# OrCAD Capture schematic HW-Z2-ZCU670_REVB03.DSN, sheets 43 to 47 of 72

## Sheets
43 043 Power Input Fan Controller: size Custom
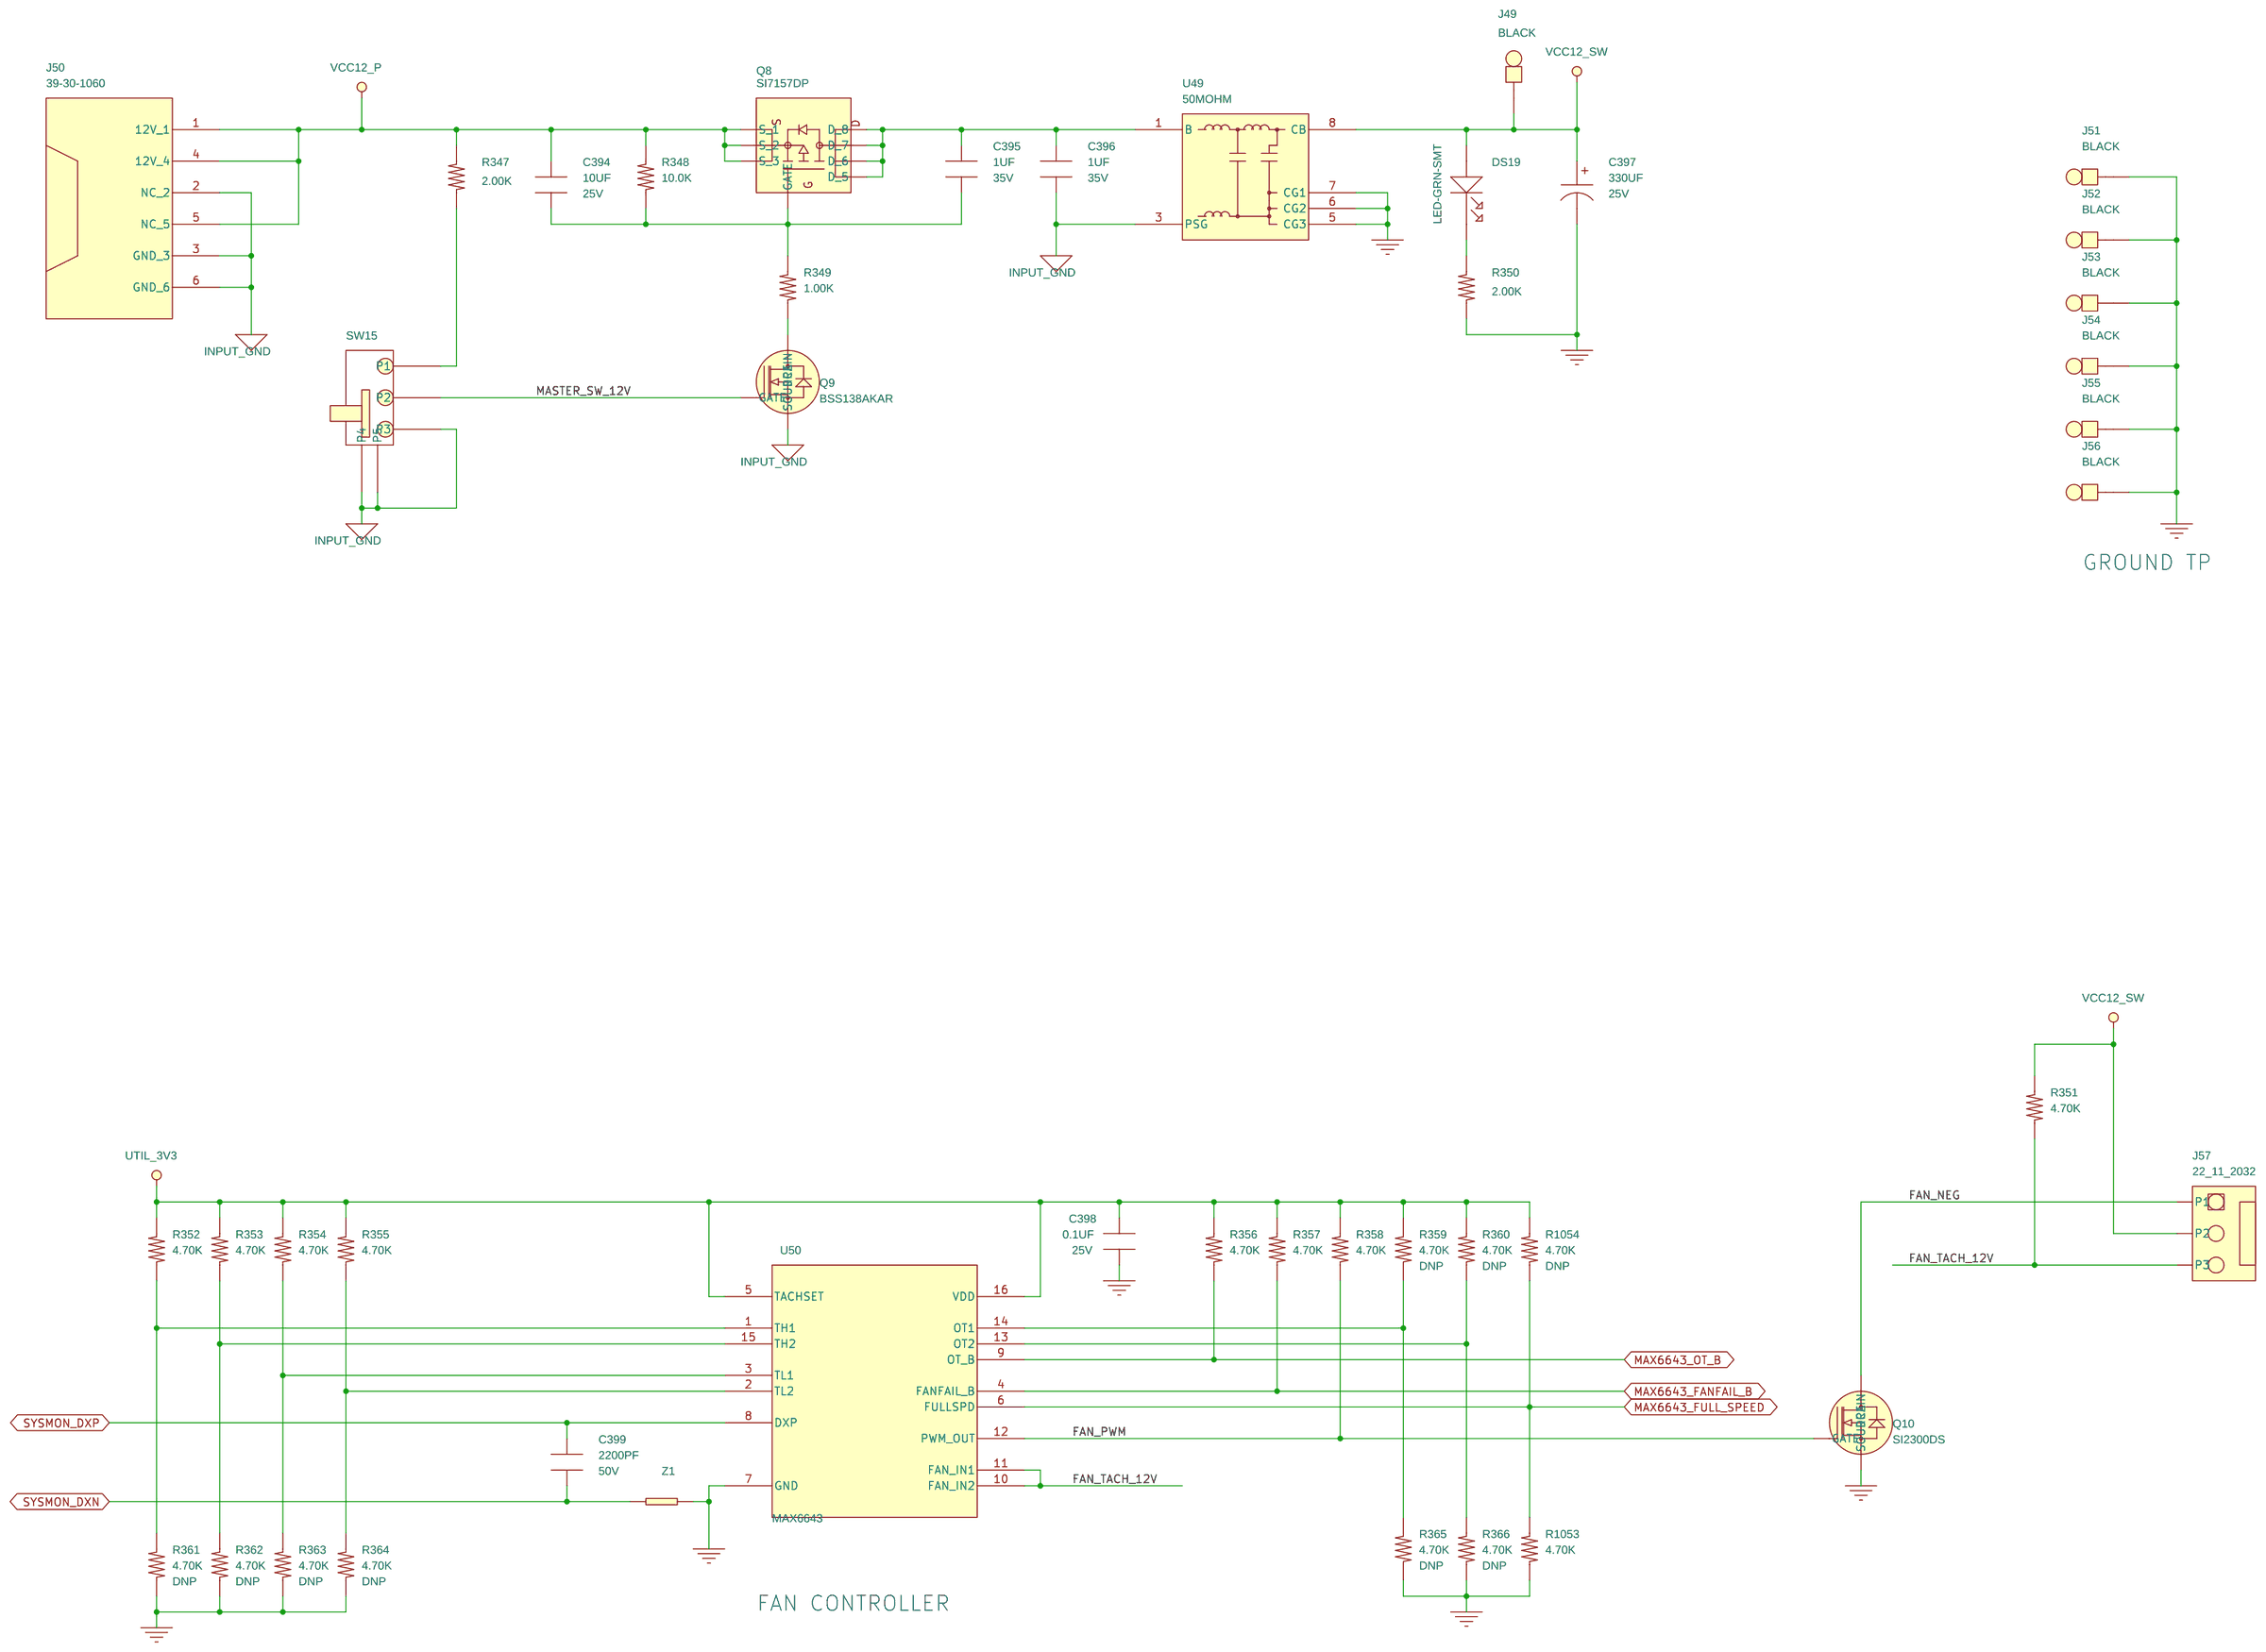
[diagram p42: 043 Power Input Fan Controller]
44 044 VCCINT - VCCINT_AMS PMIC1: size Custom
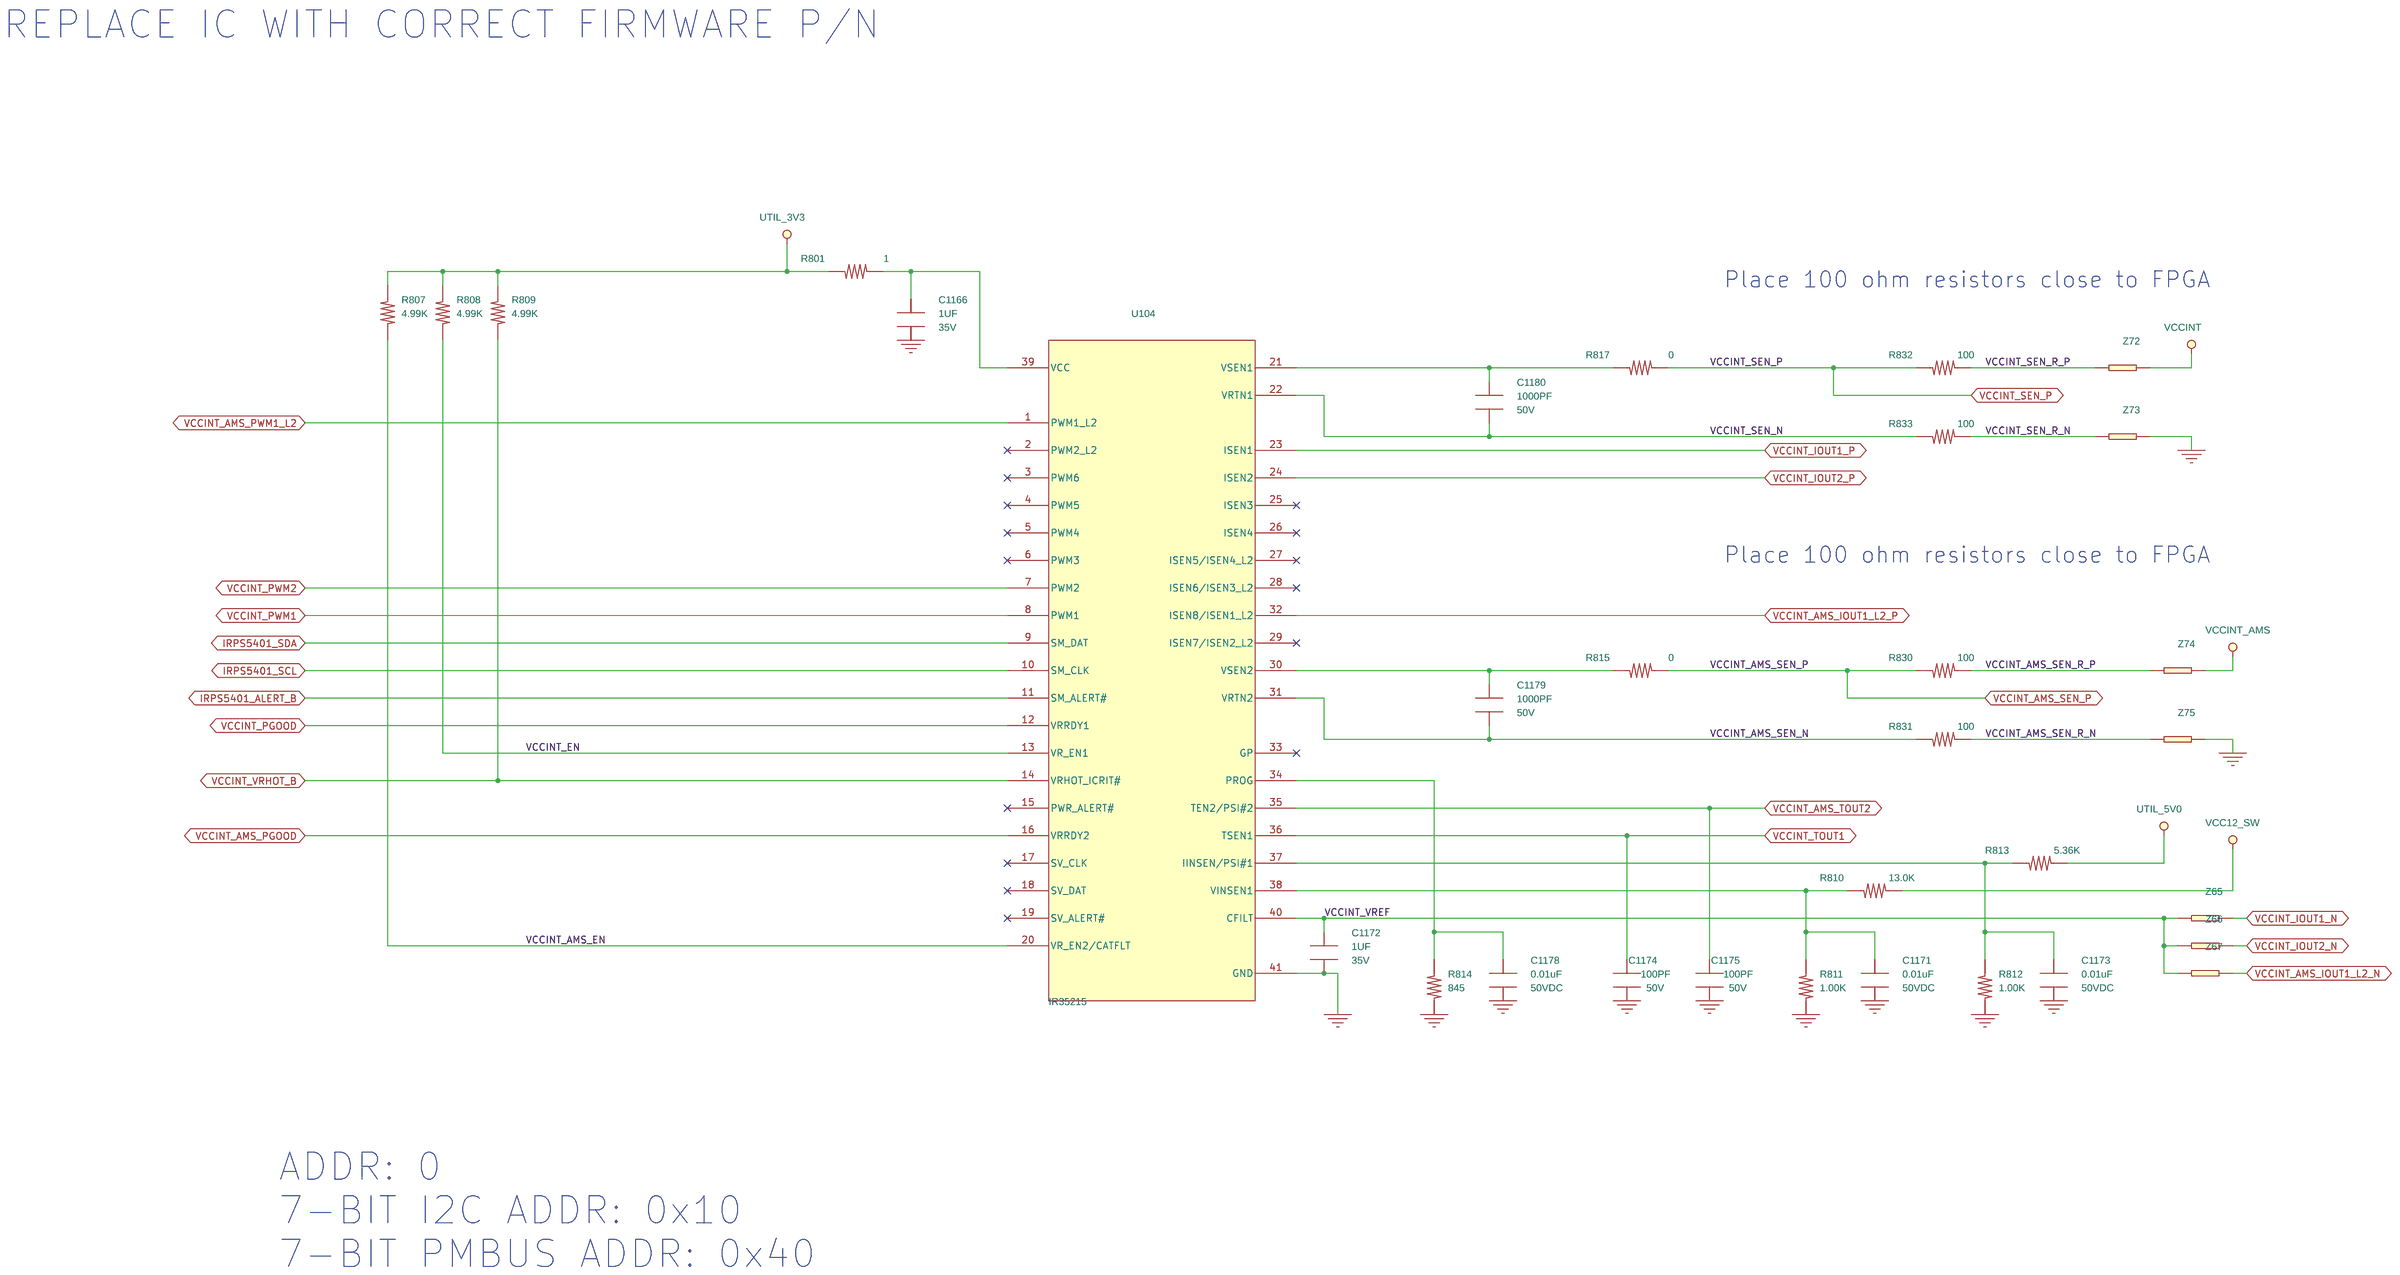
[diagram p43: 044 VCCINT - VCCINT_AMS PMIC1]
45 045 VCCINT - VCCINT_AMS Stages: size Custom
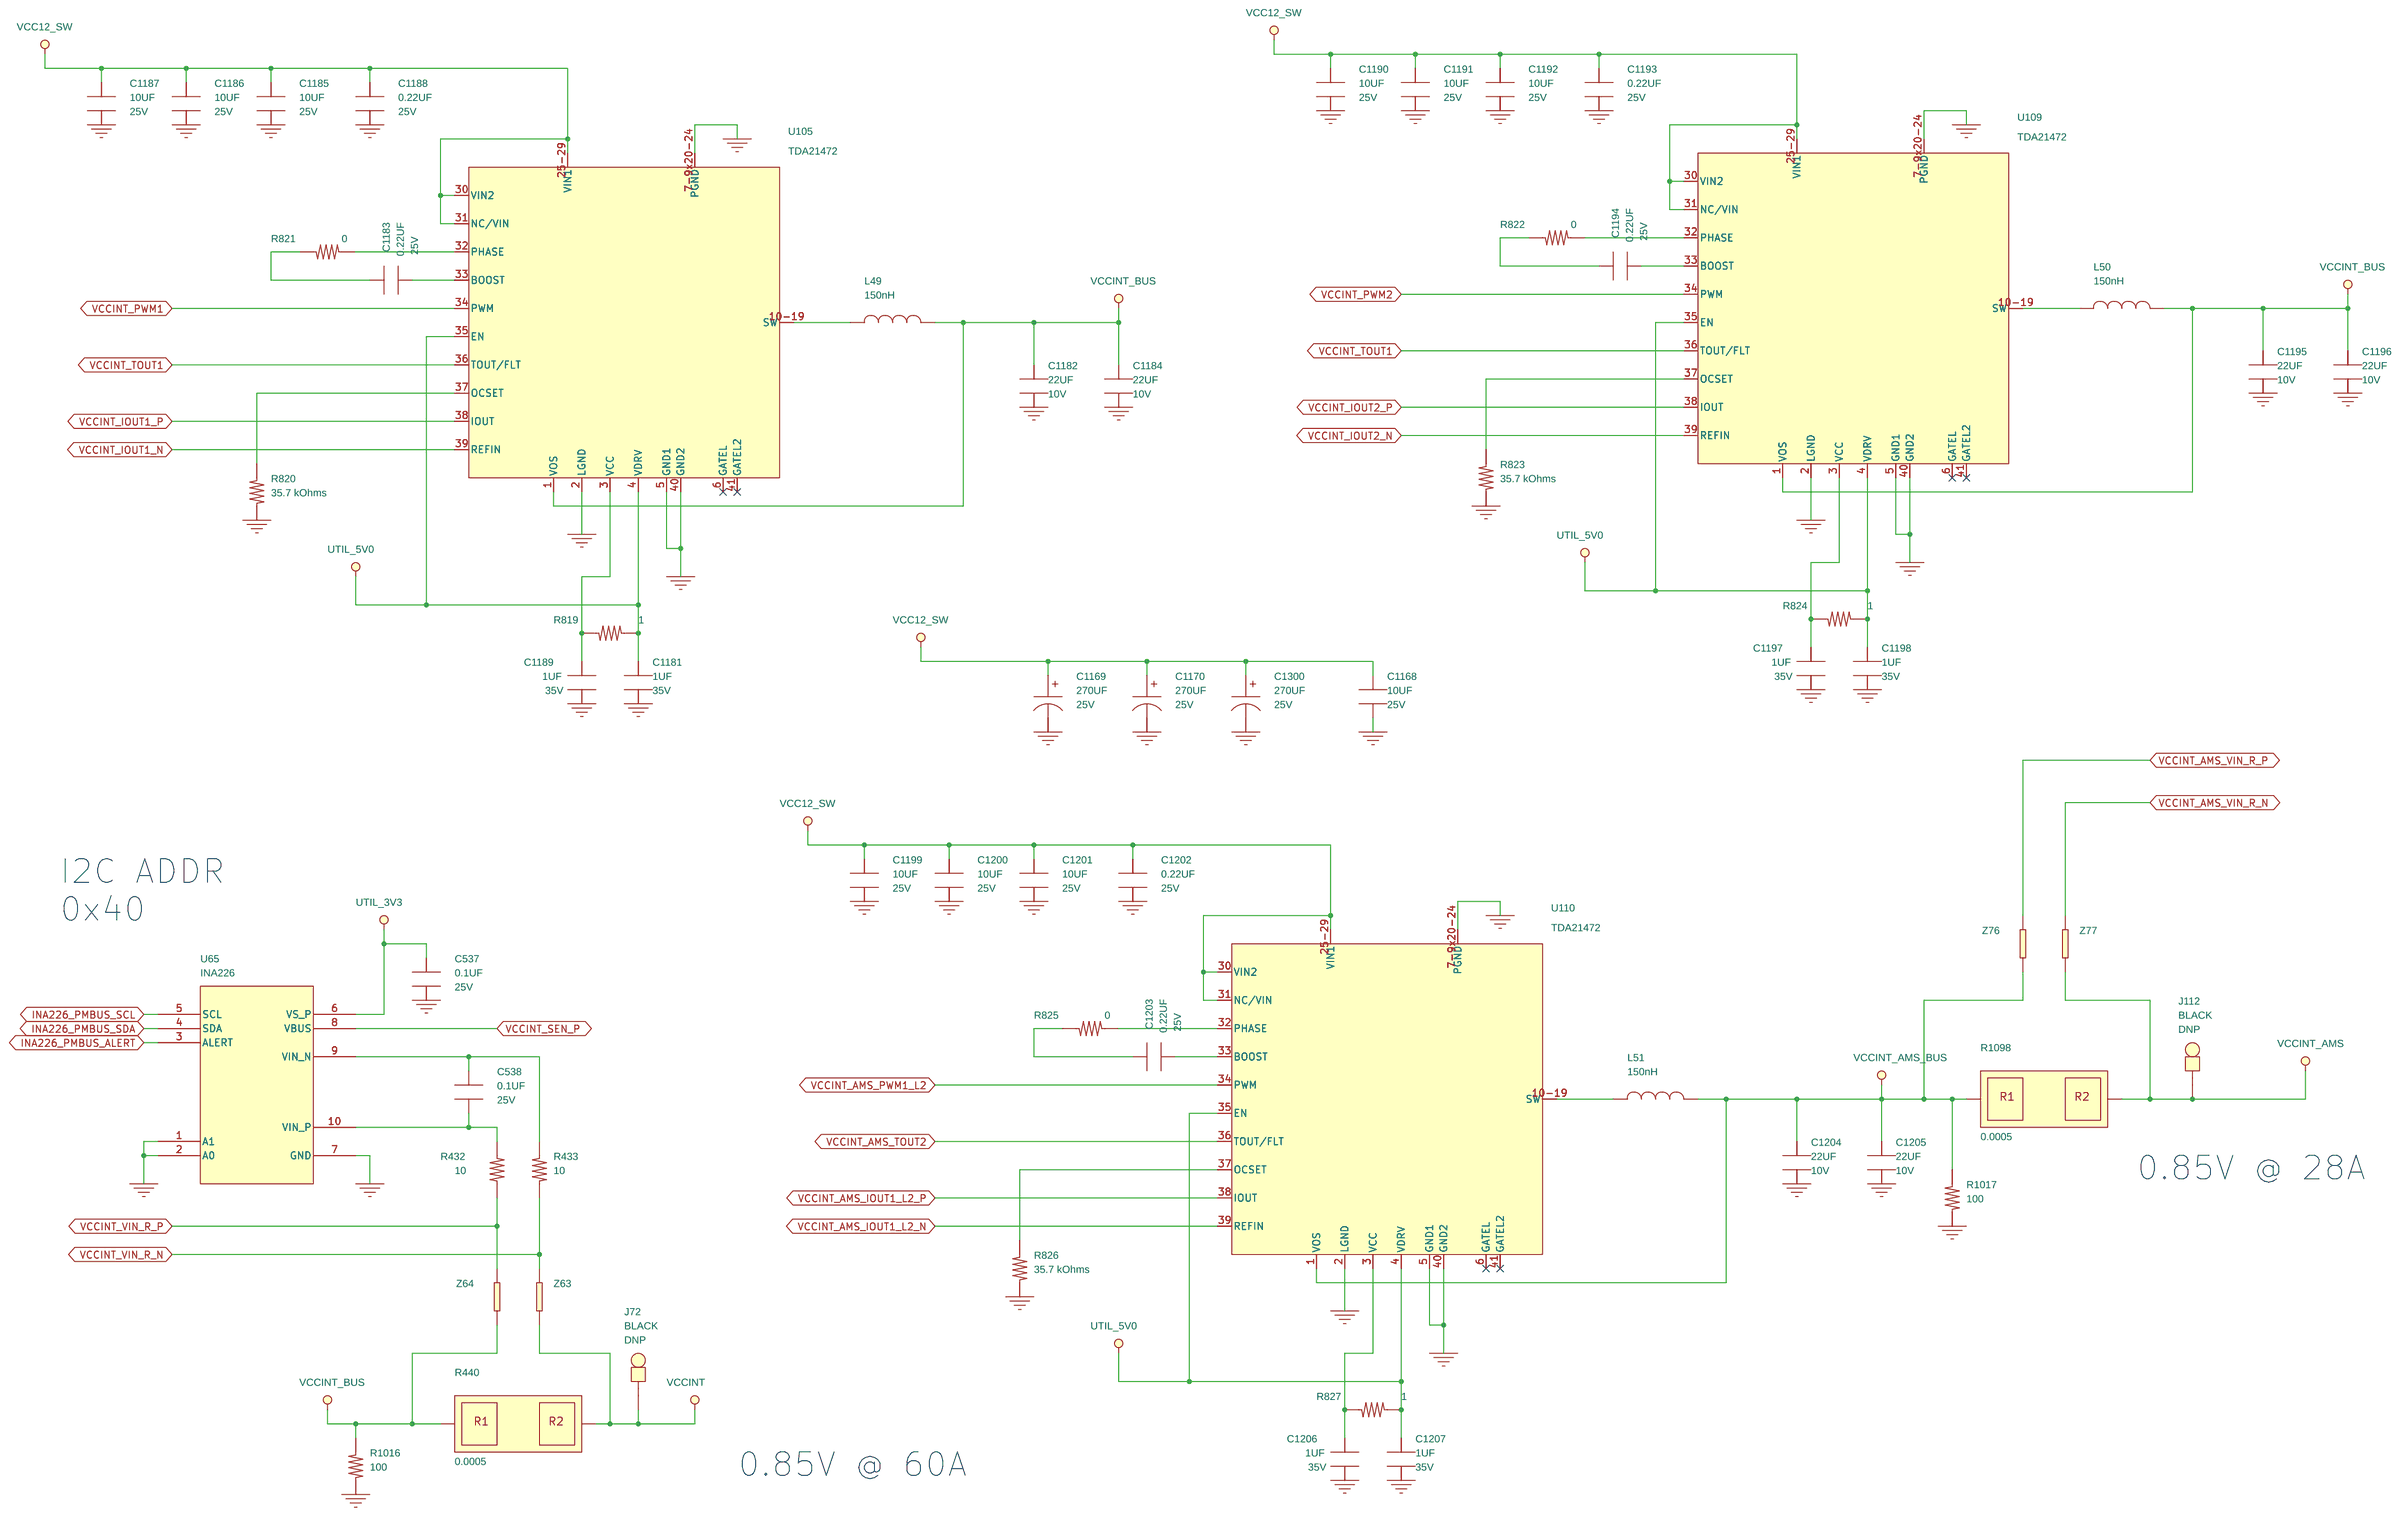
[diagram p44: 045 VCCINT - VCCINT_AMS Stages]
46 046 VCCINT - VCCINT_AMS Decap: size Custom
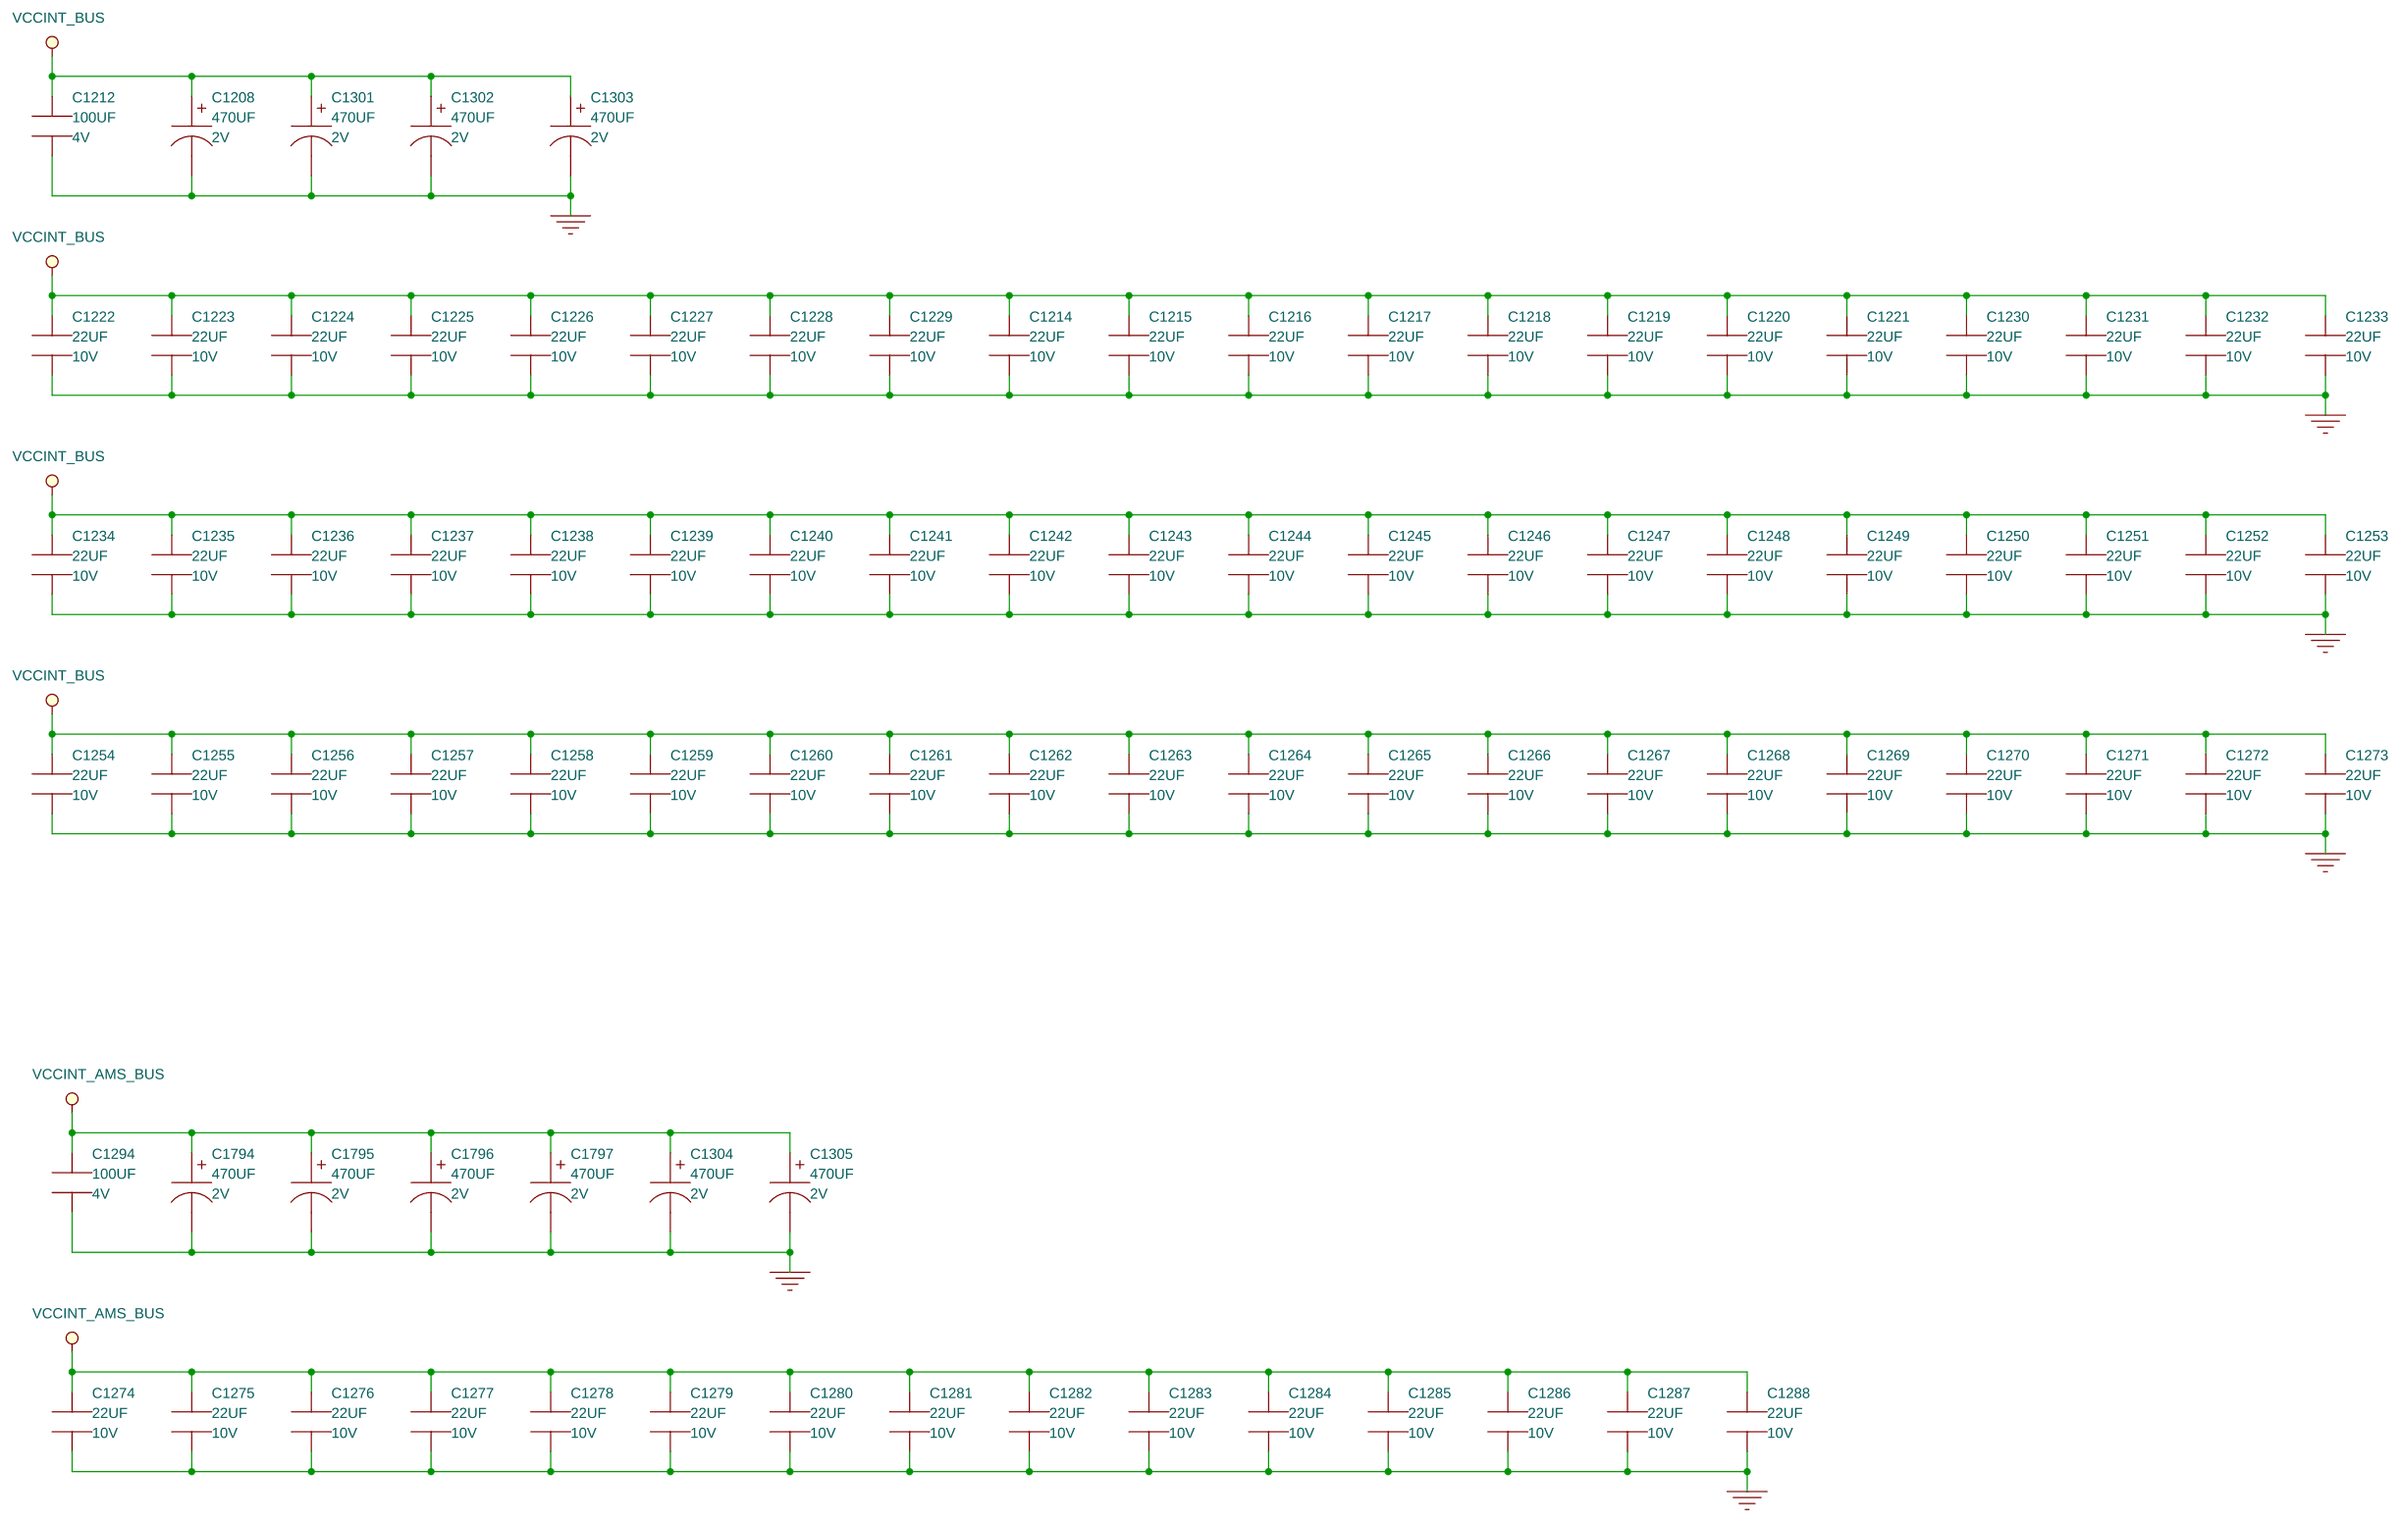
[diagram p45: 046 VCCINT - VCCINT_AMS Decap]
47 047 PMIC 2: size Custom
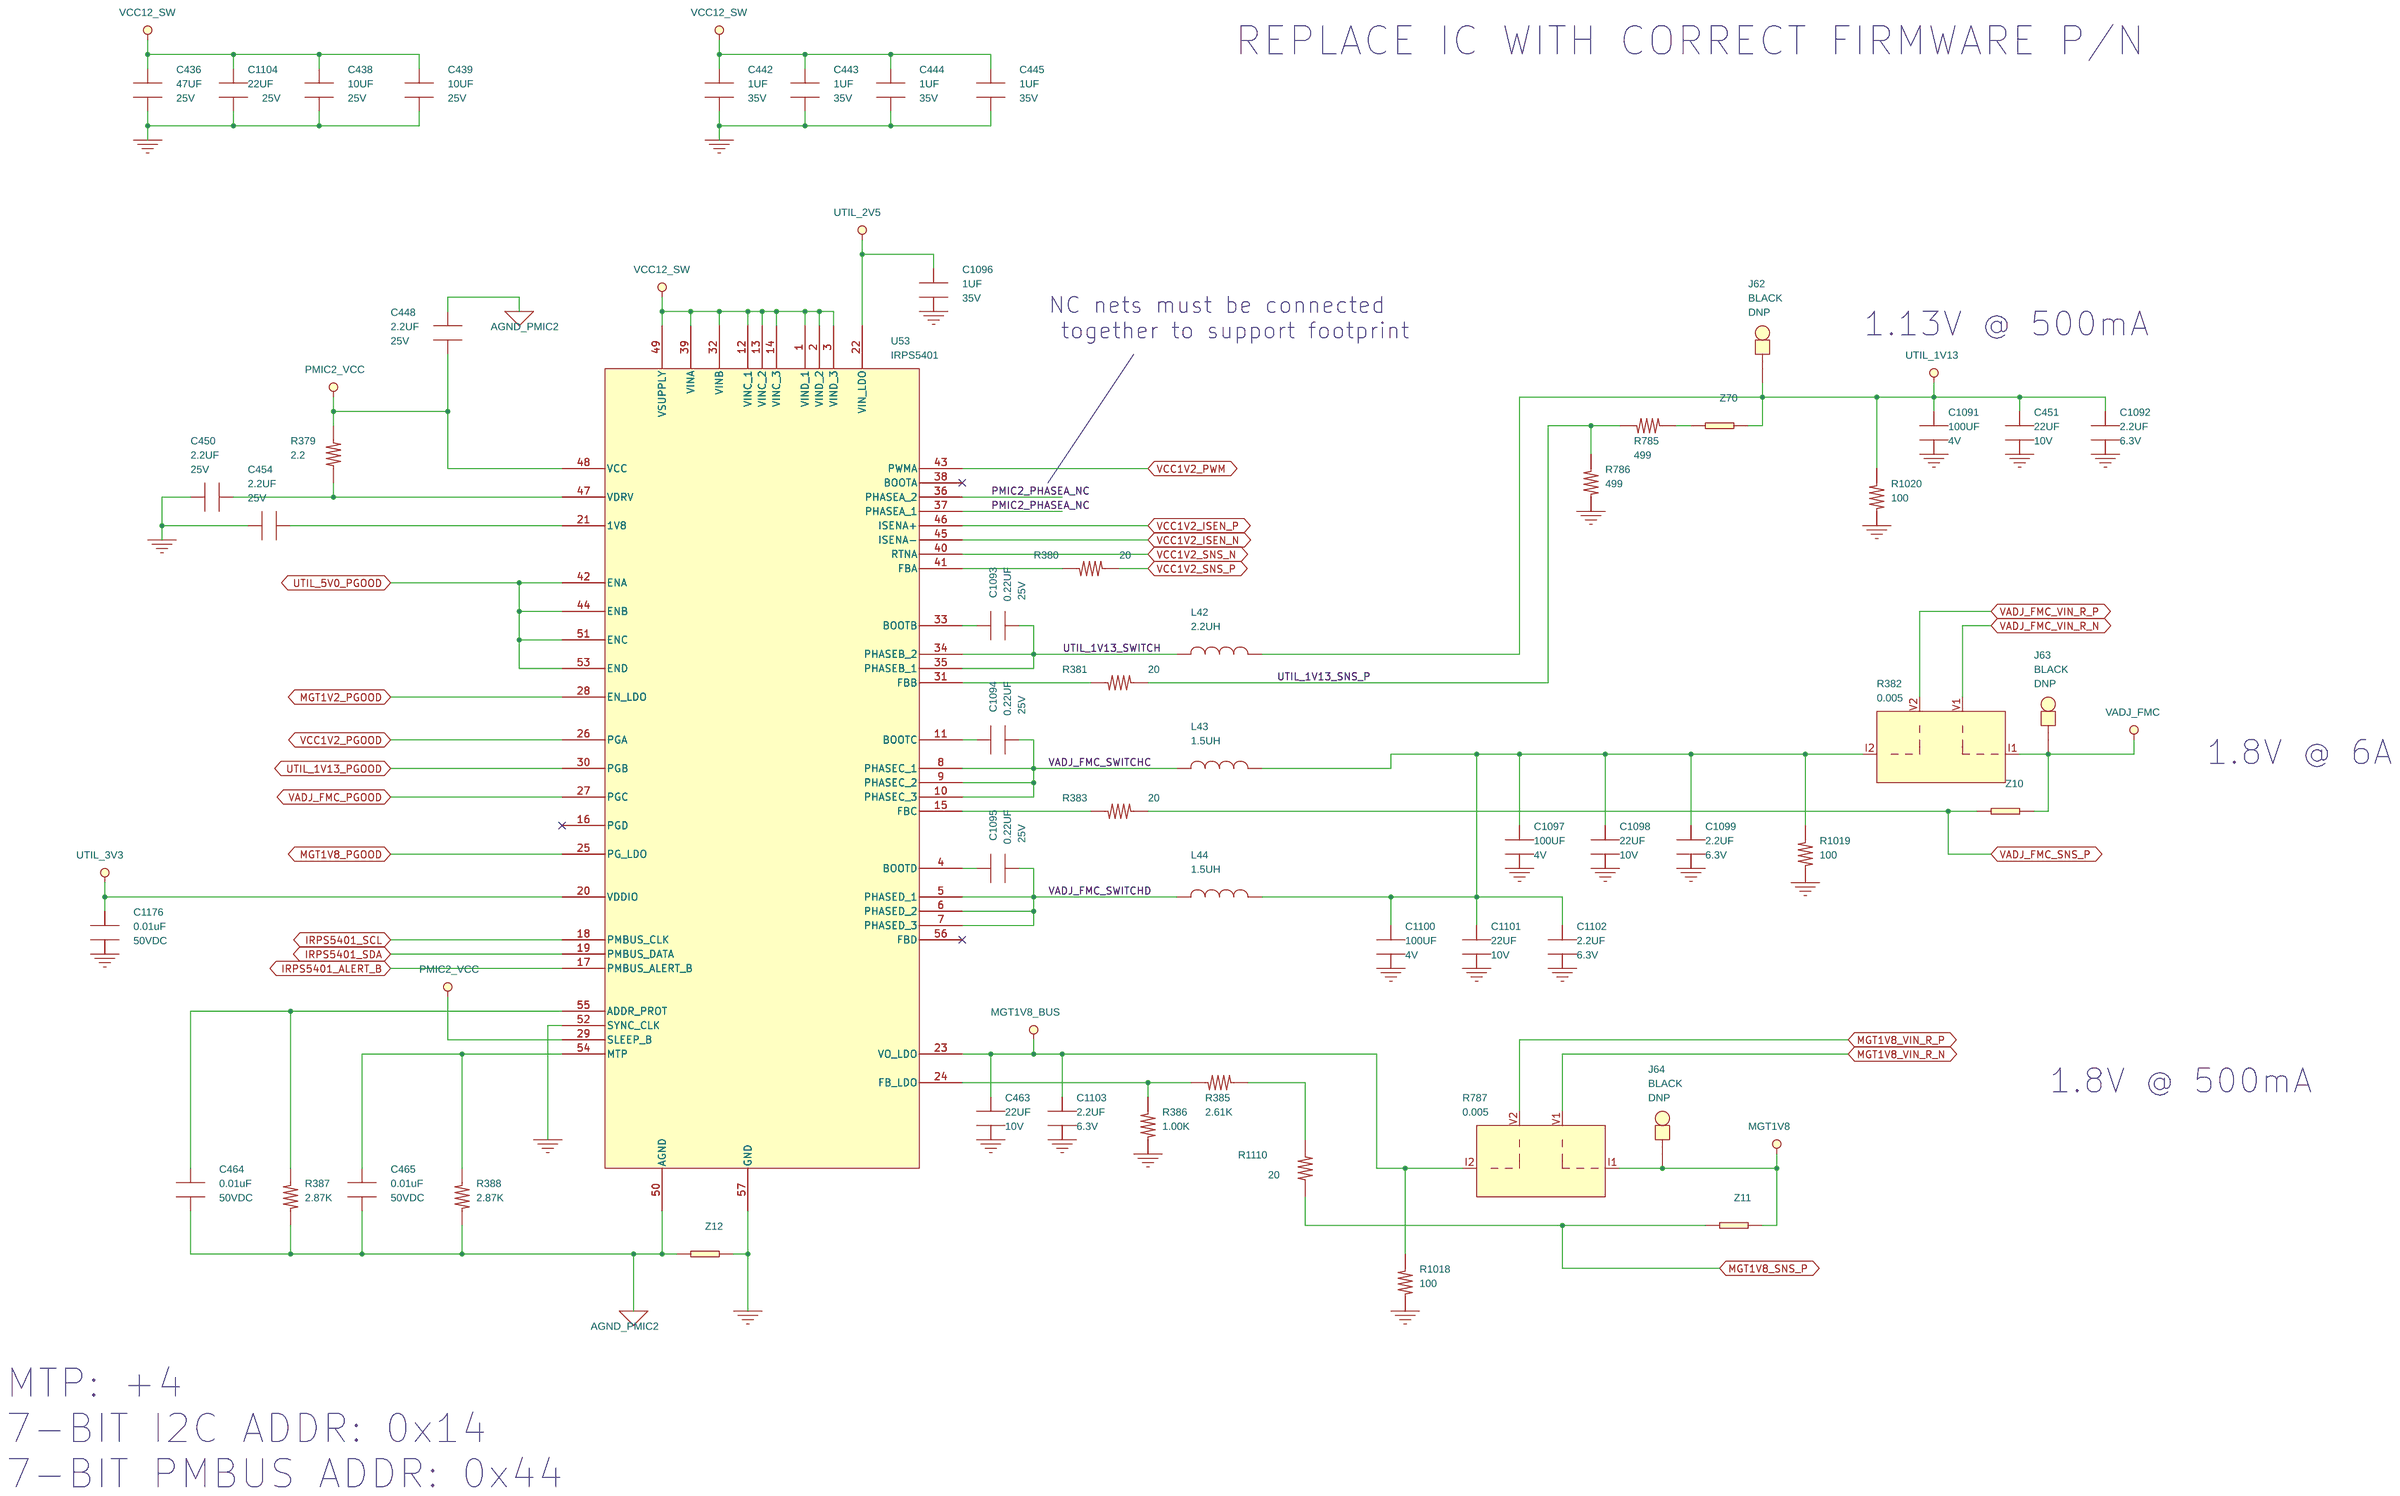
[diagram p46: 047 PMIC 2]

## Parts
sheet 043 Power Input Fan Controller
C394  10UF  [CAPC320X250X220]
C395  1UF  [CAPC100X50X60]
C396  1UF  [CAPC100X50X60]
C397  330UF  [CAPR_800_350]
C398  0.1UF  [CAPC100X50X55]
C399  2200PF  [CAPC100X50X55]
DS19  LED-GRN-SMT  [LED_0603]
J49  BLACK  [TP_KEY_MINI]
J50  39-30-1060  [CON_MOL_5569_6P]
J51  BLACK  [TP_KEY_MINI]
J52  BLACK  [TP_KEY_MINI]
J53  BLACK  [TP_KEY_MINI]
J54  BLACK  [TP_KEY_MINI]
J55  BLACK  [TP_KEY_MINI]
J56  BLACK  [TP_KEY_MINI]
J57  22_11_2032  [HDR_1X3_LOCK_MOLEX]
Q8  SI7157DP  [PWR_56_V02]
Q9  BSS138AKAR  [SOT_23]
Q10  SI2300DS  [SOT_23]
R347  2.00K  [RESC100X50X40]
R348  10.0K  [RESC100X50X40]
R349  1.00K  [RESC100X50X40]
R350  2.00K  [RESC100X50X40]
R351  4.70K  [RESC100X50X40]
R352  4.70K  [RESC100X50X40]
R353  4.70K  [RESC100X50X40]
R354  4.70K  [RESC100X50X40]
R355  4.70K  [RESC100X50X40]
R356  4.70K  [RESC100X50X40]
R357  4.70K  [RESC100X50X40]
R358  4.70K  [RESC100X50X40]
R359  4.70K  [RESC100X50X40]
R360  4.70K  [RESC100X50X40]
R361  4.70K  [RESC100X50X40]
R362  4.70K  [RESC100X50X40]
R363  4.70K  [RESC100X50X40]
R364  4.70K  [RESC100X50X40]
R365  4.70K  [RESC100X50X40]
R366  4.70K  [RESC100X50X40]
R1053  4.70K  [RESC100X50X40]
R1054  4.70K  [RESC100X50X40]
SW15  1101M2S3AQE2  [SW_102_1261_EV]
U49  50MOHM  [MURATA_BNX01]
U50  MAX6643  [QSOP16_MAX_E16_1]
Z1  0201_SHORT  [0201_SHORT]
sheet 044 VCCINT - VCCINT_AMS PMIC1
C1166  1UF  [CAPC100X50X60]
C1171  0.01uF  [CAPC100X50X55]
C1172  1UF  [CAPC100X50X60]
C1173  0.01uF  [CAPC100X50X55]
C1174  100PF  [CAPC100X50X55]
C1175  100PF  [CAPC100X50X55]
C1178  0.01uF  [CAPC100X50X55]
C1179  1000PF  [CAPC100X50X55]
C1180  1000PF  [CAPC100X50X55]
R801  1  [RESC160X80X55]
R807  4.99K  [RESC100X50X40]
R808  4.99K  [RESC100X50X40]
R809  4.99K  [RESC100X50X40]
R810  13.0K  [RESC100X50X40]
R811  1.00K  [RESC100X50X40]
R812  1.00K  [RESC100X50X40]
R813  5.36K  [RESC100X50X40]
R814  845  [RESC100X50X40]
R815  0  [RESC100X50X40]
R817  0  [RESC100X50X40]
R830  100  [RESC100X50X40]
R831  100  [RESC100X50X40]
R832  100  [RESC100X50X40]
R833  100  [RESC100X50X40]
U104  IR35215  [QFN04P500X500X85_40_370]
Z65  0201_SHORT  [0201_SHORT]
Z66  0201_SHORT  [0201_SHORT]
Z67  0201_SHORT  [0201_SHORT]
Z72  0201_SHORT  [0201_SHORT]
Z73  0201_SHORT  [0201_SHORT]
Z74  0201_SHORT  [0201_SHORT]
Z75  0201_SHORT  [0201_SHORT]
sheet 045 VCCINT - VCCINT_AMS Stages
C537  0.1UF  [CAPC100X50X55]
C538  0.1UF  [CAPC100X50X55]
C1168  10UF  [CAPC320X250X220]
C1169  270UF  [CAPR_800_350]
C1170  270UF  [CAPR_800_350]
C1181  1UF  [CAPC100X50X60]
C1182  22UF  [CAPC200X125X145]
C1183  0.22UF  [CAPC100X50X55]
C1184  22UF  [CAPC200X125X145]
C1185  10UF  [CAPC320X250X220]
C1186  10UF  [CAPC320X250X220]
C1187  10UF  [CAPC320X250X220]
C1188  0.22UF  [CAPC100X50X55]
C1189  1UF  [CAPC100X50X60]
C1190  10UF  [CAPC320X250X220]
C1191  10UF  [CAPC320X250X220]
C1192  10UF  [CAPC320X250X220]
C1193  0.22UF  [CAPC100X50X55]
C1194  0.22UF  [CAPC100X50X55]
C1195  22UF  [CAPC200X125X145]
C1196  22UF  [CAPC200X125X145]
C1197  1UF  [CAPC100X50X60]
C1198  1UF  [CAPC100X50X60]
C1199  10UF  [CAPC320X250X220]
C1200  10UF  [CAPC320X250X220]
C1201  10UF  [CAPC320X250X220]
C1202  0.22UF  [CAPC100X50X55]
C1203  0.22UF  [CAPC100X50X55]
C1204  22UF  [CAPC200X125X145]
C1205  22UF  [CAPC200X125X145]
C1206  1UF  [CAPC100X50X60]
C1207  1UF  [CAPC100X50X60]
C1300  270UF  [CAPR_800_350]
J72  BLACK  [TP_KEY_MINI]
J112  BLACK  [TP_KEY_MINI]
L49  150nH  [IND_EATON_FP10007R3]
L50  150nH  [IND_EATON_FP10007R3]
L51  150nH  [IND_EATON_FP10007R3]
R432  10  [RESC100X50X40]
R433  10  [RESC100X50X40]
R440  0.0005  [RES_CSS2775]
R819  1  [RESC160X80X55]
R820  35.7 kOhms  [RESC100X50X40]
R821  0  [RESC100X50X40]
R822  0  [RESC100X50X40]
R823  35.7 kOhms  [RESC100X50X40]
R824  1  [RESC160X80X55]
R825  0  [RESC100X50X40]
R826  35.7 kOhms  [RESC100X50X40]
R827  1  [RESC160X80X55]
R1016  100  [RESC100X50X40]
R1017  100  [RESC100X50X40]
R1098  0.0005  [RES_CSS2775]
U65  INA226  [DGS_MSOP_10]
U105  TDA21472  [PQFN_TDA21472_41]
U109  TDA21472  [PQFN_TDA21472_41]
U110  TDA21472  [PQFN_TDA21472_41]
Z63  0201_SHORT  [0201_SHORT]
Z64  0201_SHORT  [0201_SHORT]
Z76  0201_SHORT  [0201_SHORT]
Z77  0201_SHORT  [0201_SHORT]
sheet 046 VCCINT - VCCINT_AMS Decap
C1208  470UF  [TANT_D]
C1212  100UF  [CAPC200X125X145]
C1214  22UF  [CAPC200X125X145]
C1215  22UF  [CAPC200X125X145]
C1216  22UF  [CAPC200X125X145]
C1217  22UF  [CAPC200X125X145]
C1218  22UF  [CAPC200X125X145]
C1219  22UF  [CAPC200X125X145]
C1220  22UF  [CAPC200X125X145]
C1221  22UF  [CAPC200X125X145]
C1222  22UF  [CAPC200X125X145]
C1223  22UF  [CAPC200X125X145]
C1224  22UF  [CAPC200X125X145]
C1225  22UF  [CAPC200X125X145]
C1226  22UF  [CAPC200X125X145]
C1227  22UF  [CAPC200X125X145]
C1228  22UF  [CAPC200X125X145]
C1229  22UF  [CAPC200X125X145]
C1230  22UF  [CAPC200X125X145]
C1231  22UF  [CAPC200X125X145]
C1232  22UF  [CAPC200X125X145]
C1233  22UF  [CAPC200X125X145]
C1234  22UF  [CAPC200X125X145]
C1235  22UF  [CAPC200X125X145]
C1236  22UF  [CAPC200X125X145]
C1237  22UF  [CAPC200X125X145]
C1238  22UF  [CAPC200X125X145]
C1239  22UF  [CAPC200X125X145]
C1240  22UF  [CAPC200X125X145]
C1241  22UF  [CAPC200X125X145]
C1242  22UF  [CAPC200X125X145]
C1243  22UF  [CAPC200X125X145]
C1244  22UF  [CAPC200X125X145]
C1245  22UF  [CAPC200X125X145]
C1246  22UF  [CAPC200X125X145]
C1247  22UF  [CAPC200X125X145]
C1248  22UF  [CAPC200X125X145]
C1249  22UF  [CAPC200X125X145]
C1250  22UF  [CAPC200X125X145]
C1251  22UF  [CAPC200X125X145]
C1252  22UF  [CAPC200X125X145]
C1253  22UF  [CAPC200X125X145]
C1254  22UF  [CAPC200X125X145]
C1255  22UF  [CAPC200X125X145]
C1256  22UF  [CAPC200X125X145]
C1257  22UF  [CAPC200X125X145]
C1258  22UF  [CAPC200X125X145]
C1259  22UF  [CAPC200X125X145]
C1260  22UF  [CAPC200X125X145]
C1261  22UF  [CAPC200X125X145]
C1262  22UF  [CAPC200X125X145]
C1263  22UF  [CAPC200X125X145]
C1264  22UF  [CAPC200X125X145]
C1265  22UF  [CAPC200X125X145]
C1266  22UF  [CAPC200X125X145]
C1267  22UF  [CAPC200X125X145]
C1268  22UF  [CAPC200X125X145]
C1269  22UF  [CAPC200X125X145]
C1270  22UF  [CAPC200X125X145]
C1271  22UF  [CAPC200X125X145]
C1272  22UF  [CAPC200X125X145]
C1273  22UF  [CAPC200X125X145]
C1274  22UF  [CAPC200X125X145]
C1275  22UF  [CAPC200X125X145]
C1276  22UF  [CAPC200X125X145]
C1277  22UF  [CAPC200X125X145]
C1278  22UF  [CAPC200X125X145]
C1279  22UF  [CAPC200X125X145]
C1280  22UF  [CAPC200X125X145]
C1281  22UF  [CAPC200X125X145]
C1282  22UF  [CAPC200X125X145]
C1283  22UF  [CAPC200X125X145]
C1284  22UF  [CAPC200X125X145]
C1285  22UF  [CAPC200X125X145]
C1286  22UF  [CAPC200X125X145]
C1287  22UF  [CAPC200X125X145]
C1288  22UF  [CAPC200X125X145]
C1294  100UF  [CAPC200X125X145]
C1301  470UF  [TANT_D]
C1302  470UF  [TANT_D]
C1303  470UF  [TANT_D]
C1304  470UF  [TANT_D]
C1305  470UF  [TANT_D]
C1794  470UF  [TANT_D]
C1795  470UF  [TANT_D]
C1796  470UF  [TANT_D]
C1797  470UF  [TANT_D]
sheet 047 PMIC 2
C436  47UF  [CAPC320X160X180]
C438  10UF  [CAPC320X250X220]
C439  10UF  [CAPC320X250X220]
C442  1UF  [CAPC100X50X60]
C443  1UF  [CAPC100X50X60]
C444  1UF  [CAPC100X50X60]
C445  1UF  [CAPC100X50X60]
C448  2.2UF  [CAPC200X125X135]
C450  2.2UF  [CAPC200X125X135]
C451  22UF  [CAPC200X125X145]
C454  2.2UF  [CAPC200X125X135]
C463  22UF  [CAPC200X125X145]
C464  0.01uF  [CAPC100X50X55]
C465  0.01uF  [CAPC100X50X55]
C1091  100UF  [CAPC200X125X145]
C1092  2.2UF  [CAPC100X50X55]
C1093  0.22UF  [CAPC100X50X55]
C1094  0.22UF  [CAPC100X50X55]
C1095  0.22UF  [CAPC100X50X55]
C1096  1UF  [CAPC100X50X60]
C1097  100UF  [CAPC200X125X145]
C1098  22UF  [CAPC200X125X145]
C1099  2.2UF  [CAPC100X50X55]
C1100  100UF  [CAPC200X125X145]
C1101  22UF  [CAPC200X125X145]
C1102  2.2UF  [CAPC100X50X55]
C1103  2.2UF  [CAPC100X50X55]
C1104  22UF  [CAPC320X160X180]
C1176  0.01uF  [CAPC100X50X55]
J62  BLACK  [TP_KEY_MINI]
J63  BLACK  [TP_KEY_MINI]
J64  BLACK  [TP_KEY_MINI]
L42  2.2UH  [IND_SRP4020TA]
L43  1.5UH  [IND_SRP4020TA]
L44  1.5UH  [IND_SRP4020TA]
R379  2.2  [RESC160X80X55]
R380  20  [RESC100X50X40]
R381  20  [RESC100X50X40]
R382  0.005  [1224_SMT]
R383  20  [RESC100X50X40]
R385  2.61K  [RESC100X50X40]
R386  1.00K  [RESC100X50X40]
R387  2.87K  [RESC100X50X40]
R388  2.87K  [RESC100X50X40]
R785  499  [RESC100X50X40]
R786  499  [RESC100X50X40]
R787  0.005  [1224_SMT]
R1018  100  [RESC100X50X40]
R1019  100  [RESC100X50X40]
R1020  100  [RESC100X50X40]
R1110  20  [RESC100X50X40]
U53  IRPS5401  [irps5401mtrpbf]
Z10  0201_SHORT  [0201_SHORT]
Z11  0201_SHORT  [0201_SHORT]
Z12  0201_SHORT  [0201_SHORT]
Z70  0201_SHORT  [0201_SHORT]

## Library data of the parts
C394 C438 C439 C1168 C1185-C1187 C1190-C1192 C1199-C1201 = CAP_NP: Cap Cer 10uF 10% 25V X5R 1210; ALT_SYMBOLS: CAPC320X250X220RND; Agile Part Number: CAP-00113-01; CIP Link: http://xsjbrdwin1/CIP-E/Component/Index/All?pn=100123; Dielectric Type: X5R; OWNER: 3709; PRICE: 0.18; Part Type: CERAMIC; PartType: CERAMIC; ROHS: Yes; Tolerance: 10%; Voltage: 25V; barcode: 100123
C395 C396 C442-C445 C1096 C1166 C1172 C1181 C1189 C1197 C1198 C1206 C1207 = CAP_NP: Cap Cer 1uF 10% 35V X5R 0402; ALT_SYMBOLS: CAPC100X50X60RND; Agile Part Number: CAP-00165-01; CIP Link: http://xsjbrdwin1/CIP-E/Component/Index/All?pn=100192; Dielectric Type: X5R; OWNER: 3709; PRICE: 0.04; Part Type: CERAMIC; PartType: CERAMIC; ROHS: Yes; Tolerance: 10%; Voltage: 35V; barcode: 100192
C397 = CAP_P: Cap Alum 330uF 20% 25V 8x15mm 3.5mm P TH 105C; Agile Part Number: CAP-00053-01; CIP Link: http://xsjbrdwin1/CIP-E/Component/Index/All?pn=100021; Dielectric Type: ELEC; ESR: 41mohms; Equivalent Series Resistance: 41mohms; OWNER: 3501; PRICE: 0.14; Part Type: ELECTROLYTIC; PartType: ELECTROLYTIC; ROHS: Yes; Tolerance: 20%; Voltage: 25V; barcode: 100021
C398 C537 C538 = CAP_NP: Cap Cer 100nF 10% 25V X5R 0402; ALT_SYMBOLS: CAPC100X50X55RND; Agile Part Number: CAP-00068-01; CIP Link: http://xsjbrdwin1/CIP-E/Component/Index/All?pn=100040; Dielectric Type: X5R; OWNER: 4001; PRICE: 0.01; Part Type: CERAMIC; PartType: CERAMIC; ROHS: Yes; Tolerance: 10%; Voltage: 25V; barcode: 100040
C399 = CAP_NP: Cap Cer 2.2nF 10% 50V X7R 0402; ALT_SYMBOLS: CAPC100X50X55RND; Agile Part Number: CAP-00030-01; CIP Link: http://xsjbrdwin1/CIP-E/Component/Index/All?pn=100095; Dielectric Type: X7R; OWNER: 3709; PRICE: 0; Part Type: CERAMIC; PartType: CERAMIC; ROHS: Yes; Tolerance: 10%; Voltage: 50V; barcode: 100095
DS19 = LED: LED Green Diffused 20mA 5V 570nm 0603; Agile Part Number: DIO-00003-01; Barcode: 300021; CIP Link: http://xsjbrdwin1/CIP-E/Component/Index/All?pn=300021; OWNER: 4001; PRICE: 0.1; Power: 2.2-20MA; ROHS: Yes; Rated Power: 2.2-20MA; Voltage: 2.2V
J49 J62-J64 J72 J112 = TP-HOOK: Conn Test Point Mini Loop Black TH; ALT_SYMBOLS: TP_KEY_MINI_DNP; ASSEMBLY_OPTIONS: DNP; Agile Part Number: CON-00272-01; Barcode: 900015; CIP Link: http://xsjbrdwin1/CIP-E/Component/Index/All?pn=900015; OWNER: 3709; Part Type: TEST POINT; PartType: TEST POINT; Pins: 1PIN; Pitch: 0.04IN; ROHS: Yes
J50 = 12V_RT_ANGLE_MINI_FIT_JACK: Conn Hdr RA 6 Pos 2x3 4.2mm P Natural TH with Pegs; Agile Part Number: CON-00106-01; Barcode: 400022; CIP Link: http://xsjbrdwin1/CIP-E/Component/Index/All?pn=400022; OWNER: 4001; PRICE: 0.65; Part Type: DC-PWR-JACK; PartType: DC-PWR-JACK; Pins: 6PINS; Pitch: 0.165; ROHS: Yes
J51-J56 = TP-HOOK: Conn Test Point Mini Loop Black TH; ALT_SYMBOLS: TP_KEY_MINI_DNP; Agile Part Number: CON-00272-01; Barcode: 900015; CIP Link: http://xsjbrdwin1/CIP-E/Component/Index/All?pn=900015; OWNER: 3709; Part Type: TEST POINT; PartType: TEST POINT; Pins: 1PIN; Pitch: 0.04IN; ROHS: Yes
J57 = FANHDR3: Conn Hdr Male Vert 3 Pos 1x3 2.54mm P Natural TH Friction Lock; Agile Part Number: CON-00295-01; Barcode: 40000012; CIP Link: http://xsjbrdwin1/CIP-E/Component/Index/All?pn=40000012; Number of Pins: 3 Position; OWNER: 3709; PRICE: 0.44; Part Type: FAN HEADER; PartType: FAN HEADER; Pins: 3PINS; Pitch: 2.54 mm; ROHS: Yes
Q8 = SI7157DP: MOSFET P-Ch 20V 60A 1.6mR Power PAK SO-8; Agile Part Number: TRN-00027-01; Barcode: 500377; CIP Link: http://xsjbrdwin1/CIP-E/Component/Index/All?pn=500377; OWNER: 3501; PRICE: 0; Part Type: FET; PartType: FET; Power: 104W; ROHS: Yes; Rated Power: 104W; Rated Voltage: 20V
Q9 = FET-3PIN: MOSFET N-Ch 60V 200mA 4.5R SOT-23; Agile Part Number: TRN-00044-01; Barcode: 83000003; CIP Link: http://xsjbrdwin1/CIP-E/Component/Index/All?pn=83000003; OWNER: 3501; PRICE: 0.1; Part Type: Discrete Semiconductor Products\Surface Mount; PartType: FET; Power: 360MW; ROHS: Yes; Rated Power: 300mW (Ta), 1.06W (Tc)
Q10 = FET-3PIN: MOSFET N-Ch 30V 3.6A 68mR SOT-23; Agile Part Number: TRN-00014-01; Barcode: 500105; CIP Link: http://xsjbrdwin1/CIP-E/Component/Index/All?pn=500105; OWNER: 3709; PRICE: 0.14; Part Type: FET; PartType: FET; Power: 1.7W; ROHS: Yes; Rated Power: 1.7W; Rated Voltage: 30V
R347 R350 = RES: Res 2K 1% 1/16W 100PPM 50V 0402; ALT_SYMBOLS: RESC100X50X40RND; Agile Part Number: RES-00003-01; Barcode: 200096; CIP Link: http://xsjbrdwin1/CIP-E/Component/Index/All?pn=200096; OWNER: 4001; PRICE: 0.05; Part Type: SMT - 1%; PartType: SMT - 1%; Power: 1/16W; ROHS: Yes; Rated Power: 1/16W; Tolerance: 1%; primarykey: 2
R348 = RES: Res 10K 1% 1/16W 100PPM 50V 0402; ALT_SYMBOLS: RESC100X50X40RND; Agile Part Number: RES-00030-01; Barcode: 200025; CIP Link: http://xsjbrdwin1/CIP-E/Component/Index/All?pn=200025; OWNER: 4001; PRICE: 0; Part Type: SMT - 1%; PartType: SMT - 1%; Power: 1/10W; ROHS: Yes; Rated Power: 1/16W; Tolerance: 1%; primarykey: 1
R349 = RES: Res 1K 1% 1/16W 100PPM 50V 0402; ALT_SYMBOLS: RESC100X50X40RND; Agile Part Number: RES-00027-01; Barcode: 200098; CIP Link: http://xsjbrdwin1/CIP-E/Component/Index/All?pn=200098; OWNER: 4001; PRICE: 0; Part Type: SMT - 1%; PartType: SMT - 1%; Power: 1/16W; ROHS: Yes; Rated Power: 1/16W; Tolerance: 1%; primarykey: 7
R351-R358 R1053 = RES: Res 4K7 1% 1/16W 100PPM 50V 0402; ALT_SYMBOLS: RESC100X50X40RND; Agile Part Number: RES-00035-01; Barcode: 200067; CIP Link: http://xsjbrdwin1/CIP-E/Component/Index/All?pn=200067; OWNER: 3670; PRICE: 0.01; Part Type: SMT - 1%; PartType: SMT - 1%; Power: 1/16W; ROHS: Yes; Rated Power: 1/16W; Tolerance: 1%; primarykey: 128
R359-R366 R1054 = RES: Res 4K7 1% 1/16W 100PPM 50V 0402; ALT_SYMBOLS: RESC100X50X40RND; ASSEMBLY_OPTIONS: DNP; Agile Part Number: RES-00035-01; Barcode: 200067; CIP Link: http://xsjbrdwin1/CIP-E/Component/Index/All?pn=200067; OWNER: 3709; PRICE: 0; Part Type: SMT - 1%; PartType: SMT - DNP; Power: DNP; ROHS: Yes; Rated Power: 1/16W; Tolerance: 1%; primarykey: 73
SW15 = SW_SLIDE_SPDT: Switch SPDT Slide 6A 120VAC 6.6mm H Black TH; Agile Part Number: SWH-00019-01; Barcode: 440016; CIP Link: http://xsjbrdwin1/CIP-E/Component/Index/All?pn=440016; OWNER: 3709; PRICE: 2.69; Part Type: SPDT; PartType: SPDT; ROHS: Yes
U49 = BNX016-01: EMIFIL 50R 15A 0.8mR 40 dB Attn 100KHz - 1GHz 12x11mm TH; Agile Part Number: FLT-00008-01; Barcode: 300030; CIP Link: http://xsjbrdwin1/CIP-E/Component/Index/All?pn=300030; OWNER: 3709; Part Type: COMBINED; PartType: COMBINED; ROHS: Yes
U50 = MAX6643: IC PWM Cont 1-Phase QSOP-16 Temp Sense; Agile Part Number: ICS-00341-01; Barcode: 500509; CIP Link: http://xsjbrdwin1/CIP-E/Component/Index/All?pn=500509; Family: THERMAL MANAGEMENT; Part Type: THERMAL MANAGEMENT; ROHS: Yes
Z1 Z10-Z12 Z63-Z67 Z70 Z72-Z77 = 0201_SHORT: PCB only 0201_SHORT; ASSEMBLY_OPTIONS: DNP; Barcode: 96000001; CIP Link: http://xsjbrdwin1/CIP-E/Component/Index/All?pn=96000001; OWNER: 3670; Part Type: PCB LAYOUT; PartType: PCB LAYOUT; ROHS: 0
C464 C465 C1171 C1173 C1176 C1178 = CAP_NP: Cap Cer 10nF 10% 50V X7R 0402; ALT_SYMBOLS: CAPC100X50X55RND; Agile Part Number: CAP-00031-01; CIP Link: http://xsjbrdwin1/CIP-E/Component/Index/All?pn=100003; Dielectric Type: X7R; OWNER: 4001; PRICE: 0; Part Type: CERAMIC; PartType: CERAMIC; ROHS: Yes; Tolerance: 10%; Voltage: 50VDC; barcode: 100003
C1174 C1175 = CAP_NP: Cap Cer 100pF 5% 50V C0G 0402; ALT_SYMBOLS: CAPC100X50X55RND; Agile Part Number: CAP-00161-01; CIP Link: http://xsjbrdwin1/CIP-E/Component/Index/All?pn=100187; Dielectric Type: NP0; OWNER: 4001; PRICE: 0.01; Part Type: CERAMIC; PartType: CERAMIC; ROHS: Yes; Tolerance: 5%; Voltage: 50V; barcode: 100187
C1179 C1180 = CAP_NP: Cap Cer 1nF 10% 50V X7R 0402; ALT_SYMBOLS: CAPC100X50X55RND; Agile Part Number: CAP-00036-01; Barcode: 100013; CIP Link: http://xsjbrdwin1/CIP-E/Component/Index/All?pn=100013; Dielectric Type: X7R; Part Type: CERAMIC; Tolerance: 10%; Voltage: 50V
R801 R819 R824 R827 = RES: Res 1R 1% 1/10W 200PPM 0603; ALT_SYMBOLS: RESC160X80X55RND; Agile Part Number: RES-00391-01; Barcode: 200437; CIP Link: http://xsjbrdwin1/CIP-E/Component/Index/All?pn=200437; Part Type: SMT - 1%; Rated Power: 1/10W; Tolerance: 1%
R807-R809 = RES: Res 4K99 1% 1/16W 100PPM 50V 0402; ALT_SYMBOLS: RESC100X50X40RND; Agile Part Number: RES-00004-01; Barcode: 200072; CIP Link: http://xsjbrdwin1/CIP-E/Component/Index/All?pn=200072; Part Type: SMT - 1%; Rated Power: 1/16W; Tolerance: 1%
R810 = RES: Res 13K 1% 1/16W 100PPM 50V 0402; ALT_SYMBOLS: (0402,C402-25,RESC100X50X40L25NRND); Agile Part Number: RES-00036-01; Barcode: 200341; CIP Link: http://xsjbrdwin1/CIP-E/Component/Index/All?pn=200341; Part Type: SMT - 1%; Rated Power: 1/16W; Tolerance: 1%
R811 R812 = RES: Res 1K 1% 1/16W 100PPM 50V 0402; ALT_SYMBOLS: RESC100X50X40RND; Agile Part Number: RES-00027-01; Barcode: 200098; CIP Link: http://xsjbrdwin1/CIP-E/Component/Index/All?pn=200098; Part Type: SMT - 1%; Rated Power: 1/16W; Tolerance: 1%
R813 = RES: Res 5K36 1% 1/16W 100PPM 50V 0402; ALT_SYMBOLS: RESC100X50X40RND; Agile Part Number: RES-00422-01; Barcode: 200489; CIP Link: http://xsjbrdwin1/CIP-E/Component/Index/All?pn=200489; Part Type: SMT - 1%; Rated Power: 1/16W; Tolerance: 1%
R814 = RES: Res 845R 1% 1/16W 100PPM 50V 0402; Agile Part Number: RES-00313-01; Barcode: 200347; CIP Link: http://xsjbrdwin1/CIP-E/Component/Index/All?pn=200347; Part Type: SMT - 1%; Rated Power: 1/16W; Tolerance: 1%
R815 R817 R821 R822 R825 = RES: Res 0R 50mR 1A 0402; ALT_SYMBOLS: RESC100X50X40RND; Agile Part Number: RES-00010-01; Barcode: 200012; CIP Link: http://xsjbrdwin1/CIP-E/Component/Index/All?pn=200012; Part Type: SMT - 5%; Tolerance: 5%
R830-R833 R1016-R1020 = RES: Res 100R 1% 1/16W 100PPM 50V 0402; ALT_SYMBOLS: RESC100X50X40RND; Agile Part Number: RES-00046-01; Barcode: 200024; CIP Link: http://xsjbrdwin1/CIP-E/Component/Index/All?pn=200024; Part Type: SMT - 1%; Rated Power: 1/16W; Tolerance: 1%
U104 = IR35215: IC Phase Cont Dual Loop 8-Phase 3.3V 2MHz PMBus QFN-40; Agile Part Number: ICS-00513-01; Barcode: 50000034; CIP Link: http://xsjbrdwin1/CIP-E/Component/Index/All?pn=50000034; Part Type: Integrated Circuits (ICs)\--
C1169 C1170 C1300 = CAP_P: Cap Poly 270uF 20% 25V 16mR 8x12mm TH; Agile Part Number: CAP-00226-01; Barcode: 100300; CIP Link: http://xsjbrdwin1/CIP-E/Component/Index/All?pn=100300; Dielectric Type: ELEC; Equivalent Series Resistance: 16mohms; Part Type: ELECTROLYTIC; Tolerance: 20%; Voltage: 25V
C451 C463 C1098 C1101 C1182 C1184 C1195 C1196 C1204 C1205 C1214-C1288 = CAP_NP: Cap Cer 22uF 20% 10V X6S 0805; Agile Part Number: CAP-00021-01; CIP Link: http://xsjbrdwin1/CIP-E/Component/Index/All?pn=100280; Dielectric Type: X6S; OWNER: 3709; PRICE: 0.17; Part Type: CERAMIC; PartType: CERAMIC; ROHS: Yes; Tolerance: 20%; Voltage: 10V; barcode: 100280
C1093-C1095 C1183 C1188 C1193 C1194 C1202 C1203 = CAP_NP: Cap Cer 220nF 10%  25V X6S 0402; ALT_SYMBOLS: (0402,C402-25,CAPC100X50X55L25NRND,CAPC100X50X55L30NRND,CAPC100X50X55L30N); Agile Part Number: CAP-00005-01; CIP Link: http://xsjbrdwin1/CIP-E/Component/Index/All?pn=100180; Dielectric Type: X6S; OWNER: 6176; PRICE: 0.03; Part Type: CERAMIC; PartType: CERAMIC; ROHS: Yes; Tolerance: 10%; Voltage: 25V; barcode: 100180
L49-L51 = IND: Ind 150nH 10% 61A Irms 76A Isat 304.5uR 10.2x7.8mm SMT Shielded; Agile Part Number: IND-00175-01; Barcode: 30000015; CIP Link: http://xsjbrdwin1/CIP-E/Component/Index/All?pn=30000015; OWNER: 3709; PRICE: 0.5; Part Type: Inductors, Coils, Chokes\Surface Mount; PartType: POWER INDUCTOR; ROHS: YES; Tolerance: 10%
R432 R433 = RES: Res 10R 1% 1/16W 100PPM 50V 0402; ALT_SYMBOLS: RESC100X50X40RND; Agile Part Number: RES-00025-01; Barcode: 200028; CIP Link: http://xsjbrdwin1/CIP-E/Component/Index/All?pn=200028; OWNER: 10460; PRICE: 0; Part Type: SMT - 1%; PartType: SMT - 1%; Power: 1/10W; ROHS: Yes; Rated Power: 1/16W; Tolerance: 1%; primarykey: 97
R440 R1098 = RES_CS_CHIP_RESISTOR: Res 500uR 1% 4W 50PPM 2725 Wide AEC-Q200; Agile Part Number: RES-00301-01; Barcode: 200332; CIP Link: http://xsjbrdwin1/CIP-E/Component/Index/All?pn=200332; Part Type: SMT -CURSNS; Rated Power: 4W; Tolerance: 1%
R820 R823 R826 = RES: Res 35K7 1% 1/16W 100PPM 50V 0402; Agile Part Number: RES-00493-01; Barcode: 20000009; CIP Link: http://xsjbrdwin1/CIP-E/Component/Index/All?pn=20000009; Part Type: --\Thick Film\0402 (1005 Metric); Rated Power: 1/16W; Tolerance: 1%
U65 = INA226: IC Power Mon I2C 36Vin 5V VSSOP-10; Agile Part Number: ICS-00186-01; Barcode: 500247; CIP Link: http://xsjbrdwin1/CIP-E/Component/Index/All?pn=500247; Family: OPAMP; Part Type: OPAMP; ROHS: Yes
U105 U109 U110 = TDA21472: IC V. Reg Step-Down DC/DC Synch 16V 70A 1.5MHz PQFN-41; Agile Part Number: ICS-00512-01; Barcode: 50000036; CIP Link: http://xsjbrdwin1/CIP-E/Component/Index/All?pn=50000036; Part Type: Integrated Circuits (ICs)\--
C1208 C1301-C1305 C1794-C1797 = CAP_P: Cap Poly 470uF 20% 2V 3mR 7343; Agile Part Number: CAP-00128-01; Barcode: 100143; CIP Link: http://xsjbrdwin1/CIP-E/Component/Index/All?pn=100143; Dielectric Type: SP; Equivalent Series Resistance: 3mohms; Part Type: SPCAP; Tolerance: 20%; Voltage: 2V
C1091 C1097 C1100 C1212 C1294 = CAP_NP: Cap Cer 100uF 20% 4V X6S 0805; ALT_SYMBOLS: CAPC200X125X145RND; Agile Part Number: CAP-00038-01; CIP Link: http://xsjbrdwin1/CIP-E/Component/Index/All?pn=100257; Dielectric Type: X6S; OWNER: 3709; PRICE: 0.35; Part Type: CERAMIC; PartType: CERAMIC; ROHS: Yes; Tolerance: 20%; Voltage: 4V; barcode: 100257
C436 = CAP_NP: Cap Cer 47uF 20% 25V X5R 1206; ALT_SYMBOLS: CAPC320X160X180RND; Agile Part Number: CAP-00092-01; CIP Link: http://xsjbrdwin1/CIP-E/Component/Index/All?pn=100087; Dielectric Type: X5R; OWNER: 3709; PRICE: 0.18; Part Type: CERAMIC; PartType: CERAMIC; ROHS: Yes; Tolerance: 20%; Voltage: 25V; barcode: 100087
C448 C450 C454 = CAP_NP: Cap Cer 2.2uF 10% 25V X7R 0805; ALT_SYMBOLS: CAPC200X125X135RND; Agile Part Number: CAP-00114-01; CIP Link: http://xsjbrdwin1/CIP-E/Component/Index/All?pn=100124; Dielectric Type: X7R; OWNER: 3709; PRICE: 0.03; Part Type: CERAMIC; PartType: CERAMIC; ROHS: Yes; Tolerance: 10%; Voltage: 25V; barcode: 100124
C1092 C1099 C1102 C1103 = CAP_NP: Cap Cer 2.2uF 20% 6.3V X5R 0402; Agile Part Number: CAP-00081-01; CIP Link: http://xsjbrdwin1/CIP-E/Component/Index/All?pn=100062; Dielectric Type: X5R; OWNER: 6176; PRICE: 0.06; Part Type: CERAMIC; PartType: CERAMIC; ROHS: Yes; Tolerance: 20%; Voltage: 6.3V; barcode: 100062
C1104 = CAP_NP: Cap Cer 22uF 10% 25V X5R 1206; ALT_SYMBOLS: CAPC320X160X180RND; Agile Part Number: CAP-00058-01; CIP Link: http://xsjbrdwin1/CIP-E/Component/Index/All?pn=100026; Dielectric Type: X5R; OWNER: 3709; PRICE: 0.17; Part Type: CERAMIC; PartType: CERAMIC; ROHS: Yes; Tolerance: 10%; Voltage: 25V; barcode: 100026
L42 = IND: Ind 2.2uH 20% 4A Irms 6A Isat 61mR 4.45x4.06mm SMT Shielded; Agile Part Number: IND-00090-01; Barcode: 300175; CIP Link: http://xsjbrdwin1/CIP-E/Component/Index/All?pn=300175; OWNER: 3709; PRICE: 0.5; Part Type: POWER INDUCTOR; PartType: POWER INDUCTOR; ROHS: YES; Tolerance: 20%
L43 L44 = IND: Ind 1.5uH 20% 4.5A Irms 7A Isat 42mR 4.45x4.06mm SMT Shielded; Agile Part Number: IND-00091-01; Barcode: 300176; CIP Link: http://xsjbrdwin1/CIP-E/Component/Index/All?pn=300176; OWNER: 3709; PRICE: 0.5; Part Type: POWER INDUCTOR; PartType: POWER INDUCTOR; ROHS: YES; Tolerance: 20%
R379 = RES: Res 2R2 1% 1/10W 200PPM 0603; ALT_SYMBOLS: RESC160X80X55RND; Agile Part Number: RES-00241-01; Barcode: 200258; CIP Link: http://xsjbrdwin1/CIP-E/Component/Index/All?pn=200258; OWNER: 3501; PRICE: 0.01; Part Type: SMT - 1%; PartType: SMT - 1%; Power: 1/10W; ROHS: Yes; Rated Power: 1/10W; Tolerance: 1%; primarykey: 293
R380 R381 R383 R1110 = RES: Res 20R 1% 1/16W 100PPM 50V 0402; ALT_SYMBOLS: RESC100X50X40RND; Agile Part Number: RES-00033-01; Barcode: 200119; CIP Link: http://xsjbrdwin1/CIP-E/Component/Index/All?pn=200119; OWNER: 4001; PRICE: 0; Part Type: SMT - 1%; PartType: SMT - 1%; Power: 1/16W; ROHS: Yes; Rated Power: 1/16W; Tolerance: 1%; primarykey: 78
R382 R787 = RES_OHMITE_LVK25: Res 5mR 1% 2W 100PPM 1224 Wide 4-Term; Agile Part Number: RES-00118-01; Barcode: 200097; CIP Link: http://xsjbrdwin1/CIP-E/Component/Index/All?pn=200097; OWNER: 3709; PRICE: 0.89; Part Type: SMT -CURSNS; PartType: SMT -CURSNS; Power: 2W; ROHS: Yes; Rated Power: 2W; Tolerance: 1%; primarykey: 29
R385 = RES: Res 2K61 1% 1/16W 100PPM 50V 0402; ALT_SYMBOLS: (0402,C402-25,RESC100X50X40L25NRND); Agile Part Number: RES-00175-01; Barcode: 200180; CIP Link: http://xsjbrdwin1/CIP-E/Component/Index/All?pn=200180; OWNER: 6176; PRICE: 0; Part Type: SMT - 1%; PartType: SMT - 1%; Power: 1/10W; ROHS: Yes; Rated Power: 1/16W; Tolerance: 1%; primarykey: 20
R386 = RES: Res 1K 1% 1/16W 100PPM 50V 0402; ALT_SYMBOLS: RESC100X50X40RND; Agile Part Number: RES-00027-01; Barcode: 200098; CIP Link: http://xsjbrdwin1/CIP-E/Component/Index/All?pn=200098; OWNER: 3709; PRICE: 0; Part Type: SMT - 1%; PartType: SMT - 1%; Power: 1/16W; ROHS: Yes; Rated Power: 1/16W; Tolerance: 1%; primarykey: 300
R387 = RES: Res 2K87 1% 1/16W 100PPM 50V 0402; Agile Part Number: RES-00148-01; Barcode: 200138; CIP Link: http://xsjbrdwin1/CIP-E/Component/Index/All?pn=200138; OWNER: 3709; PRICE: 0; Part Type: SMT - 1%; PartType: SMT - 1%; Power: 1/10W; ROHS: Yes; Rated Power: 1/16W; Tolerance: 1%; primarykey: 137
R388 = RES: Res 2K87 1% 1/16W 100PPM 50V 0402; Agile Part Number: RES-00148-01; Barcode: 200138; CIP Link: http://xsjbrdwin1/CIP-E/Component/Index/All?pn=200138; OWNER: 3709; PRICE: 0; Part Type: SMT - 1%; PartType: SMT - 1%; Power: 1/10W; ROHS: Yes; Rated Power: 1/16W; Tolerance: 1%; primarykey: 140
R785 = RES: Res 499R 1% 1/16W 100PPM 50V 0402; ALT_SYMBOLS: RESC100X50X40RND; Agile Part Number: RES-00028-01; Barcode: 200071; CIP Link: http://xsjbrdwin1/CIP-E/Component/Index/All?pn=200071; OWNER: 6176; PRICE: 0; Part Type: SMT - 1%; PartType: SMT - 1%; Power: 1/10W; ROHS: Yes; Rated Power: 1/16W; Tolerance: 1%; primarykey: 20
R786 = RES: Res 499R 1% 1/16W 100PPM 50V 0402; ALT_SYMBOLS: RESC100X50X40RND; Agile Part Number: RES-00028-01; Barcode: 200071; CIP Link: http://xsjbrdwin1/CIP-E/Component/Index/All?pn=200071; OWNER: 3709; PRICE: 0; Part Type: SMT - 1%; PartType: SMT - 1%; Power: 1/16W; ROHS: Yes; Rated Power: 1/16W; Tolerance: 1%; primarykey: 300
U53 = IRPS5401: IC PMU 5-Ch Step-Down DC/DC 14V 2MHz I2C/PMBus QFN-56; Agile Part Number: ICS-00375-01; Barcode: 50000038; CIP Link: http://xsjbrdwin1/CIP-E/Component/Index/All?pn=50000038; Family: POWER MANAGEMENT; Part Type: POWER MANAGEMENT; ROHS: Yes

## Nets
AGND_PMIC2: C448.1 C464.2 C465.2 R387.2 R388.2 U53.50(AGND) Z12.1(NET1)
GND: C397.2 C398.2 C436.2 C438.2 C439.2 C442.2 C443.2 C444.2 C445.2 C450.2 C451.2 C454.2 C463.2 C537.2 C1091.2 C1092.2 C1096.2 C1097.2 C1098.2 C1099.2 C1100.2 C1101.2 C1102.2 C1103.2 C1104.2 C1166.2 C1168.2 C1169.2 C1170.2 C1171.1 C1172.2 C1173.1 C1174.2 C1175.2 C1176.1 C1178.1 C1181.2 C1182.2 C1184.2 C1185.2 C1186.2 C1187.2 C1188.2 C1189.2 C1190.2 C1191.2 C1192.2 C1193.2 C1195.2 C1196.2 C1197.2 C1198.2 C1199.2 C1200.2 C1201.2 C1202.2 C1204.2 C1205.2 C1206.2 C1207.2 C1208.2 C1212.2 C1214.2 C1215.2 C1216.2 C1217.2 C1218.2 C1219.2 C1220.2 C1221.2 C1222.2 C1223.2 C1224.2 C1225.2 C1226.2 C1227.2 C1228.2 C1229.2 C1230.2 C1231.2 C1232.2 C1233.2 C1234.2 C1235.2 C1236.2 C1237.2 C1238.2 C1239.2 C1240.2 C1241.2 C1242.2 C1243.2 C1244.2 C1245.2 C1246.2 C1247.2 C1248.2 C1249.2 C1250.2 C1251.2 C1252.2 C1253.2 C1254.2 C1255.2 C1256.2 C1257.2 C1258.2 C1259.2 C1260.2 C1261.2 C1262.2 C1263.2 C1264.2 C1265.2 C1266.2 C1267.2 C1268.2 C1269.2 C1270.2 C1271.2 C1272.2 C1273.2 C1274.2 C1275.2 C1276.2 C1277.2 C1278.2 C1279.2 C1280.2 C1281.2 C1282.2 C1283.2 C1284.2 C1285.2 C1286.2 C1287.2 C1288.2 C1294.2 C1300.2 C1301.2 C1302.2 C1303.2 C1304.2 C1305.2 C1794.2 C1795.2 C1796.2 C1797.2 J51.1(P1) J52.1(P1) J53.1(P1) J54.1(P1) J55.1(P1) J56.1(P1) Q10.2(SOURCE) R350.2 R361.2 R362.2 R363.2 R364.2 R365.2 R366.2 R386.2 R786.2 R811.2 R812.2 R814.2 R820.2 R823.2 R826.2 R1016.2 R1017.2 R1018.2 R1019.2 R1020.2 R1053.2 U49.5(CG3) U49.6(CG2) U49.7(CG1) U50.7(GND) U53.52(SYNC_CLK) U53.57(GND) U65.1(A1) U65.2(A0) U65.7(GND) U104.41(GND) U105.2(LGND) U105.5(GND1) U105.7-9x20-24(PGND) U105.40(GND2) U109.2(LGND) U109.5(GND1) U109.7-9x20-24(PGND) U109.40(GND2) U110.2(LGND) U110.5(GND1) U110.7-9x20-24(PGND) U110.40(GND2) Z1.2(NET2) Z12.2(NET2) Z73.2(NET2) Z75.2(NET2) ; also on sheet 3 4 5 7 8 9 10 11 12 13 14 16 17 18 19 20 21 22 23 24 25 26 27 28 32 33 34 35 36 37 38 39 40 41 42 48 49 50 51 52 53 54 55 56 57 58 59 60 61 62 63 64 65 66 67 68 69 70 71 72
VCC1V2_ISEN_N: U53.45(ISENA-) ; also on sheet 48
VCC1V2_ISEN_P: U53.46(ISENA+) ; also on sheet 48
VCC1V2_PGOOD: U53.26(PGA) ; also on sheet 59 60
VCC1V2_PWM: U53.43(PWMA) ; also on sheet 48
VCC1V2_SNS_N: U53.40(RTNA) ; also on sheet 48
VCC1V2_SNS_P: R380.2 ; also on sheet 48 56
VCC12_P: C394.1 J50.1(12V) J50.4(12V) J50.5(NC) Q8.1(S) Q8.2(S) Q8.3(S) R347.1 R348.1
VCC12_SW: C397.1 C436.1 C438.1 C439.1 C442.1 C443.1 C444.1 C445.1 C1104.1 C1168.1 C1169.1 C1170.1 C1185.1 C1186.1 C1187.1 C1188.1 C1190.1 C1191.1 C1192.1 C1193.1 C1199.1 C1200.1 C1201.1 C1202.1 C1300.1 DS19.2 J49.1(P1) J57.2(P2) R351.1 R810.2 U49.8(CB) U53.1(VIND) U53.2(VIND) U53.3(VIND) U53.12(VINC_1) U53.13(VINC_2) U53.14(VINC_3) U53.32(VINB) U53.39(VINA) U53.49(VSUPPLY) U105.25-29(VIN1) U105.30(VIN2) U105.31(NC/VIN) U109.25-29(VIN1) U109.30(VIN2) U109.31(NC/VIN) U110.25-29(VIN1) U110.30(VIN2) U110.31(NC/VIN) ; also on sheet 28 31 48 49 50 51 52 57 58 62
VCCINT: J72.1(P1) R440.2 Z63.1(NET1) Z72.2(NET2) ; also on sheet 3 15 17 69
VCCINT_AMS: J112.1(P1) R1098.2 Z74.2(NET2) Z77.1(NET1) ; also on sheet 15 69
VCCINT_AMS_BUS: C1204.1 C1205.1 C1274.1 C1275.1 C1276.1 C1277.1 C1278.1 C1279.1 C1280.1 C1281.1 C1282.1 C1283.1 C1284.1 C1285.1 C1286.1 C1287.1 C1288.1 C1294.1 C1304.1 C1305.1 C1794.1 C1795.1 C1796.1 C1797.1 L51.2 R1017.1 R1098.1 U110.1(VOS) Z76.1(NET1)
VCCINT_AMS_EN: R807.2 U104.20(VR_EN2/CATFLT)
VCCINT_AMS_IOUT1_L2_N: U110.39(REFIN) Z67.2(NET2)
VCCINT_AMS_IOUT1_L2_P: U104.32(ISEN8/ISEN1_L2) U110.38(IOUT)
VCCINT_AMS_PGOOD: U104.16(VRRDY2) ; also on sheet 53 54 60
VCCINT_AMS_PWM1_L2: U104.1(PWM1_L2) U110.34(PWM)
VCCINT_AMS_SEN_N: C1179.2 R831.1 U104.31(VRTN2)
VCCINT_AMS_SEN_P: R815.2 R830.1 ; also on sheet 56
VCCINT_AMS_SEN_R_N: R831.2 Z75.1(NET1)
VCCINT_AMS_SEN_R_P: R830.2 Z74.1(NET1)
VCCINT_AMS_TOUT2: C1175.1 U104.35(TEN2/PSI#2) U110.36(TOUT/FLT)
VCCINT_AMS_VIN_R_N: Z77.2(NET2) ; also on sheet 56
VCCINT_AMS_VIN_R_P: Z76.2(NET2) ; also on sheet 56
VCCINT_BUS: C1182.1 C1184.1 C1195.1 C1196.1 C1208.1 C1212.1 C1214.1 C1215.1 C1216.1 C1217.1 C1218.1 C1219.1 C1220.1 C1221.1 C1222.1 C1223.1 C1224.1 C1225.1 C1226.1 C1227.1 C1228.1 C1229.1 C1230.1 C1231.1 C1232.1 C1233.1 C1234.1 C1235.1 C1236.1 C1237.1 C1238.1 C1239.1 C1240.1 C1241.1 C1242.1 C1243.1 C1244.1 C1245.1 C1246.1 C1247.1 C1248.1 C1249.1 C1250.1 C1251.1 C1252.1 C1253.1 C1254.1 C1255.1 C1256.1 C1257.1 C1258.1 C1259.1 C1260.1 C1261.1 C1262.1 C1263.1 C1264.1 C1265.1 C1266.1 C1267.1 C1268.1 C1269.1 C1270.1 C1271.1 C1272.1 C1273.1 C1301.1 C1302.1 C1303.1 L49.2 L50.2 R440.1 R1016.1 U105.1(VOS) U109.1(VOS) Z64.1(NET1)
VCCINT_EN: R808.2 U104.13(VR_EN1)
VCCINT_IOUT1_N: U105.39(REFIN) Z65.2(NET2)
VCCINT_IOUT1_P: U104.23(ISEN1) U105.38(IOUT)
VCCINT_IOUT2_N: U109.39(REFIN) Z66.2(NET2)
VCCINT_IOUT2_P: U104.24(ISEN2) U109.38(IOUT)
VCCINT_PGOOD: U104.12(VRRDY1) ; also on sheet 60
VCCINT_PWM1: U104.8(PWM1) U105.34(PWM)
VCCINT_PWM2: U104.7(PWM2) U109.34(PWM)
VCCINT_SEN_N: C1180.2 R833.1 U104.22(VRTN1)
VCCINT_SEN_P: R817.2 R832.1 U65.8(VBUS)
VCCINT_SEN_R_N: R833.2 Z73.1(NET1)
VCCINT_SEN_R_P: R832.2 Z72.1(NET1)
VCCINT_TOUT1: C1174.1 U104.36(TSEN1) U105.36(TOUT/FLT) U109.36(TOUT/FLT)
VCCINT_VIN_R_N: R433.2 Z63.2(NET2) ; also on sheet 3
VCCINT_VIN_R_P: R432.2 Z64.2(NET2) ; also on sheet 3
VCCINT_VREF: C1172.1 U104.40(CFILT) Z65.1(NET1) Z66.1(NET1) Z67.1(NET1)
VCCINT_VRHOT_B: R809.2 U104.14(VRHOT_ICRIT#) ; also on sheet 22
FAN_NEG: J57.1(P1) Q10.3(DRAIN)
FAN_PWM: Q10.1(GATE) R358.2 U50.12(PWM_OUT)
FAN_TACH_12V: J57.3(P3) R351.2 U50.10(FAN_IN2) U50.11(FAN_IN1)
INA226_PMBUS_ALERT: U65.3(ALERT) ; also on sheet 22 51 53 54 55 56
INA226_PMBUS_SCL: U65.5(SCL) ; also on sheet 22 51 53 54 55 56
INA226_PMBUS_SDA: U65.4(SDA) ; also on sheet 22 51 53 54 55 56
INPUT_GND: C396.2 J50.2(NC) J50.3(GND) J50.6(GND) Q9.2(SOURCE) SW15.3(P3) SW15.SH1(P4) SW15.SH2(P5) U49.3(PSG)
IRPS5401_ALERT_B: U53.17(PMBUS_ALERT_B) U104.11(SM_ALERT#) ; also on sheet 22 49 50 51 52
IRPS5401_SCL: U53.18(PMBUS_CLK) U104.10(SM_CLK) ; also on sheet 22 49 50 51 52
IRPS5401_SDA: U53.19(PMBUS_DATA) U104.9(SM_DAT) ; also on sheet 22 49 50 51 52
MASTER_SW_12V: Q9.1(GATE) SW15.2(P2)
MAX6643_FANFAIL_B: R357.2 U50.4(FANFAIL_B) ; also on sheet 22
MAX6643_FULL_SPEED: R1053.1 R1054.2 U50.6(FULLSPD) ; also on sheet 22
MAX6643_OT_B: R356.2 U50.9(OT_B) ; also on sheet 22
MGT1V2_PGOOD: U53.28(EN_LDO) ; also on sheet 49 60
MGT1V8: J64.1(P1) R787.I1 Z11.2(NET2) ; also on sheet 15 16 18 69
MGT1V8_BUS: C463.1 C1103.1 R787.I2 R1018.1 U53.23(VO_LDO)
MGT1V8_PGOOD: U53.25(PG_LDO) ; also on sheet 60
MGT1V8_SNS_P: R1110.1 Z11.1(NET1) ; also on sheet 56
MGT1V8_VIN_R_N: R787.V1 ; also on sheet 56
MGT1V8_VIN_R_P: R787.V2 ; also on sheet 56
PMIC2_PHASEA_NC: U53.36(PHASEA_2) U53.37(PHASEA_1)
PMIC2_VCC: C448.2 R379.1 U53.29(SLEEP_B) U53.48(VCC)
SYSMON_DXN: C399.2 Z1.1(NET1) ; also on sheet 3
SYSMON_DXP: C399.1 U50.8(DXP) ; also on sheet 3
UTIL_1V13: C451.1 C1091.1 C1092.1 J62.1(P1) L42.2 R1020.1 Z70.2(NET2) ; also on sheet 26
UTIL_1V13_PGOOD: U53.30(PGB) ; also on sheet 60
UTIL_1V13_SNS_P: R381.2 R785.1 R786.1
UTIL_1V13_SWITCH: C1093.2 L42.1 U53.34(PHASEB_2) U53.35(PHASEB_1)
UTIL_2V5: C1096.1 U53.22(VIN_LDO) ; also on sheet 26 40 49 65 66 67 68
UTIL_3V3: C398.1 C537.1 C1176.2 R352.1 R353.1 R354.1 R355.1 R356.1 R357.1 R358.1 R359.1 R360.1 R801.1 R807.1 R808.1 R809.1 R1054.1 U50.5(TACHSET) U50.16(VDD) U53.20(VDDIO) U65.6(VS_P) ; also on sheet 9 10 20 22 23 24 25 26 27 28 29 30 31 33 34 36 37 40 42 49 51 53 54 55 56 57 59 60 61 64
UTIL_5V0: C1181.1 C1198.1 C1207.1 R813.2 R819.2 R824.2 R827.2 U105.4(VDRV) U105.35(EN) U109.4(VDRV) U109.35(EN) U110.4(VDRV) U110.35(EN) ; also on sheet 20 48 53 54 55 58 60 62 64 71 72
UTIL_5V0_PGOOD: U53.42(ENA) U53.44(ENB) U53.51(ENC) U53.53(END) ; also on sheet 48 49 50 51 52 58 60
VADJ_FMC: J63.1(P1) R382.I1 Z10.2(NET2) ; also on sheet 28 29 30
VADJ_FMC_PGOOD: U53.27(PGC) ; also on sheet 28 60
VADJ_FMC_SNS_P: R383.2 Z10.1(NET1) ; also on sheet 56
VADJ_FMC_SWITCHC: C1094.2 L43.1 U53.8(PHASEC_1) U53.9(PHASEC_2) U53.10(PHASEC_3)
VADJ_FMC_SWITCHD: C1095.2 L44.1 U53.5(PHASED_1) U53.6(PHASED_2) U53.7(PHASED_3)
VADJ_FMC_VIN_R_N: R382.V1 ; also on sheet 56
VADJ_FMC_VIN_R_P: R382.V2 ; also on sheet 56
N17447295: C394.2 C395.2 Q8.4(GATE) R348.2 R349.1
N17741231: C450.1 R379.2 U53.47(VDRV)
N17741308: C454.1 U53.21(1V8)
N17816455: C464.1 R387.1 U53.55(ADDR_PROT)
N17816506: C465.1 R388.1 U53.54(MTP)
N17817228: C1093.1 U53.33(BOOTB)
N17817689: C1094.1 U53.11(BOOTC)
N17817717: C1097.1 C1098.1 C1099.1 C1100.1 C1101.1 C1102.1 L43.2 L44.2 R382.I2 R1019.1
N17818097: C1095.1 U53.4(BOOTD)
N17818795: R385.1 R386.1 U53.24(FB_LDO)
N21569944: R352.2 R361.1 U50.1(TH1)
N21569947: R353.2 R362.1 U50.15(TH2)
N21569950: R354.2 R363.1 U50.3(TL1)
N21569953: R355.2 R364.1 U50.2(TL2)
N21570657: R359.2 R365.1 U50.14(OT1)
N21570662: R360.2 R366.1 U50.13(OT2)
N21580749: C395.1 C396.1 Q8.5(D) Q8.6(D) Q8.7(D) Q8.8(D) U49.1(B)
N21580970: Q9.3(DRAIN) R349.2
N21583196: R347.2 SW15.1(P1)
N21594815: DS19.1 R350.1
N22643156: R380.1 U53.41(FBA)
N22643181: R381.1 U53.31(FBB)
N22643247: R383.1 U53.15(FBC)
N23998888: R385.2 R1110.2
N24162696: C1166.1 R801.2 U104.39(VCC)
N24164770: C1171.2 R810.1 R811.1 U104.38(VINSEN1)
N24165016: C1173.2 R812.1 R813.1 U104.37(IINSEN/PSI#1)
N24166329: C1178.2 R814.1 U104.34(PROG)
N24166698: C1179.1 R815.1 U104.30(VSEN2)
N24167382: C1180.1 R817.1 U104.21(VSEN1)
N24167790: C1189.1 R819.1 U105.3(VCC)
N24168014: L49.1 U105.10-19(SW)
N24168304: R820.1 U105.37(OCSET)
N24168354: C1183.2 U105.33(BOOST)
N24168387: C1183.1 R821.1
N24168396: R821.2 U105.32(PHASE)
N24169282: C1194.1 R822.1
N24169286: R822.2 U109.32(PHASE)
N24169304: C1194.2 U109.33(BOOST)
N24169330: L50.1 U109.10-19(SW)
N24169382: R823.1 U109.37(OCSET)
N24169418: C1197.1 R824.1 U109.3(VCC)
N24170121: C1203.1 R825.1
N24170125: R825.2 U110.32(PHASE)
N24170143: C1203.2 U110.33(BOOST)
N24170169: L51.1 U110.10-19(SW)
N24170221: R826.1 U110.37(OCSET)
N24170257: C1206.1 R827.1 U110.3(VCC)
N24172127: C538.1 R433.1 U65.9(VIN_N)
N24172149: C538.2 R432.1 U65.10(VIN_P)
N28764798: R785.2 Z70.1(NET1)

Not connected (* = marked no-connect by the designer): U53 16(PGD)* 38(BOOTA)* 56(FBD)*; U104 2(PWM2_L2)* 3(PWM6)* 4(PWM5)* 5(PWM4)* 6(PWM3)* 15(PWR_ALERT#)* 17(SV_CLK)* 18(SV_DAT)* 19(SV_ALERT#)* 25(ISEN3)* 26(ISEN4)* 27(ISEN5/ISEN4_L2)* 28(ISEN6/ISEN3_L2)* 29(ISEN7/ISEN2_L2)* 33(GP)*; U105 6(GATEL)* 41(GATEL2)*; U109 6(GATEL)* 41(GATEL2)*; U110 6(GATEL)* 41(GATEL2)*

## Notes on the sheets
sheet 43
- GROUND TP
- FAN CONTROLLER
sheet 44
- REPLACE IC WITH CORRECT FIRMWARE P/N
- Place 100 ohm resistors close to FPGA
- Place 100 ohm resistors close to FPGA
- ADDR: 0
  7-BIT I2C ADDR: 0x10
  7-BIT PMBUS ADDR: 0x40
sheet 45
- I2C ADDR
  0x40
- 0.85V @ 28A
- 0.85V @ 60A
sheet 47
- REPLACE IC WITH CORRECT FIRMWARE P/N
- NC nets must be connected
   together to support footprint
- 1.13V @ 500mA
- 1.8V @ 6A
- 1.8V @ 500mA
- MTP: +4
  7-BIT I2C ADDR: 0x14
  7-BIT PMBUS ADDR: 0x44
